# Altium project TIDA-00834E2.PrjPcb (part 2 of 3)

## Sheet TIDA-00834E2_Pg6_VOLTAGE2.SchDoc: VOLTAGE3, VOLTAGE4 AND ZCD
size 431 x 279 mm; Date: Not shown in title block; ApprovedBy: Not shown in title block; CheckedBy: Not shown in title block; Author: Not shown in title block; CompanyName: Not shown in title block; DrawnBy: Sreenivasa; Engineer: Not shown in title block; Organization: Not shown in title block; Address1: Not shown in title block; Address2: Not shown in title block; Address3: Not shown in title block; Address4: Not shown in title block; DocumentNumber: 1; Revision: Use project parameter SCH_Rev; SheetNumber: 6; SheetTotal: 10; PageSetup: Record=PageOptions¦CenterHorizontal=True¦CenterVertical=True¦PrintScale=1.00¦XCorrection=1.00¦YCorrection=1.00¦PrintKind=0¦BorderSize=5000000¦LeftOffset=0¦BottomOffset=0¦Orientation=2¦PaperLength=1000¦PaperWidth=1000¦Scale=100¦PaperSource=15¦PrintQuality=600¦MediaType=1¦DitherType=10¦PaperKind=Letter¦PrintScaleMode=1
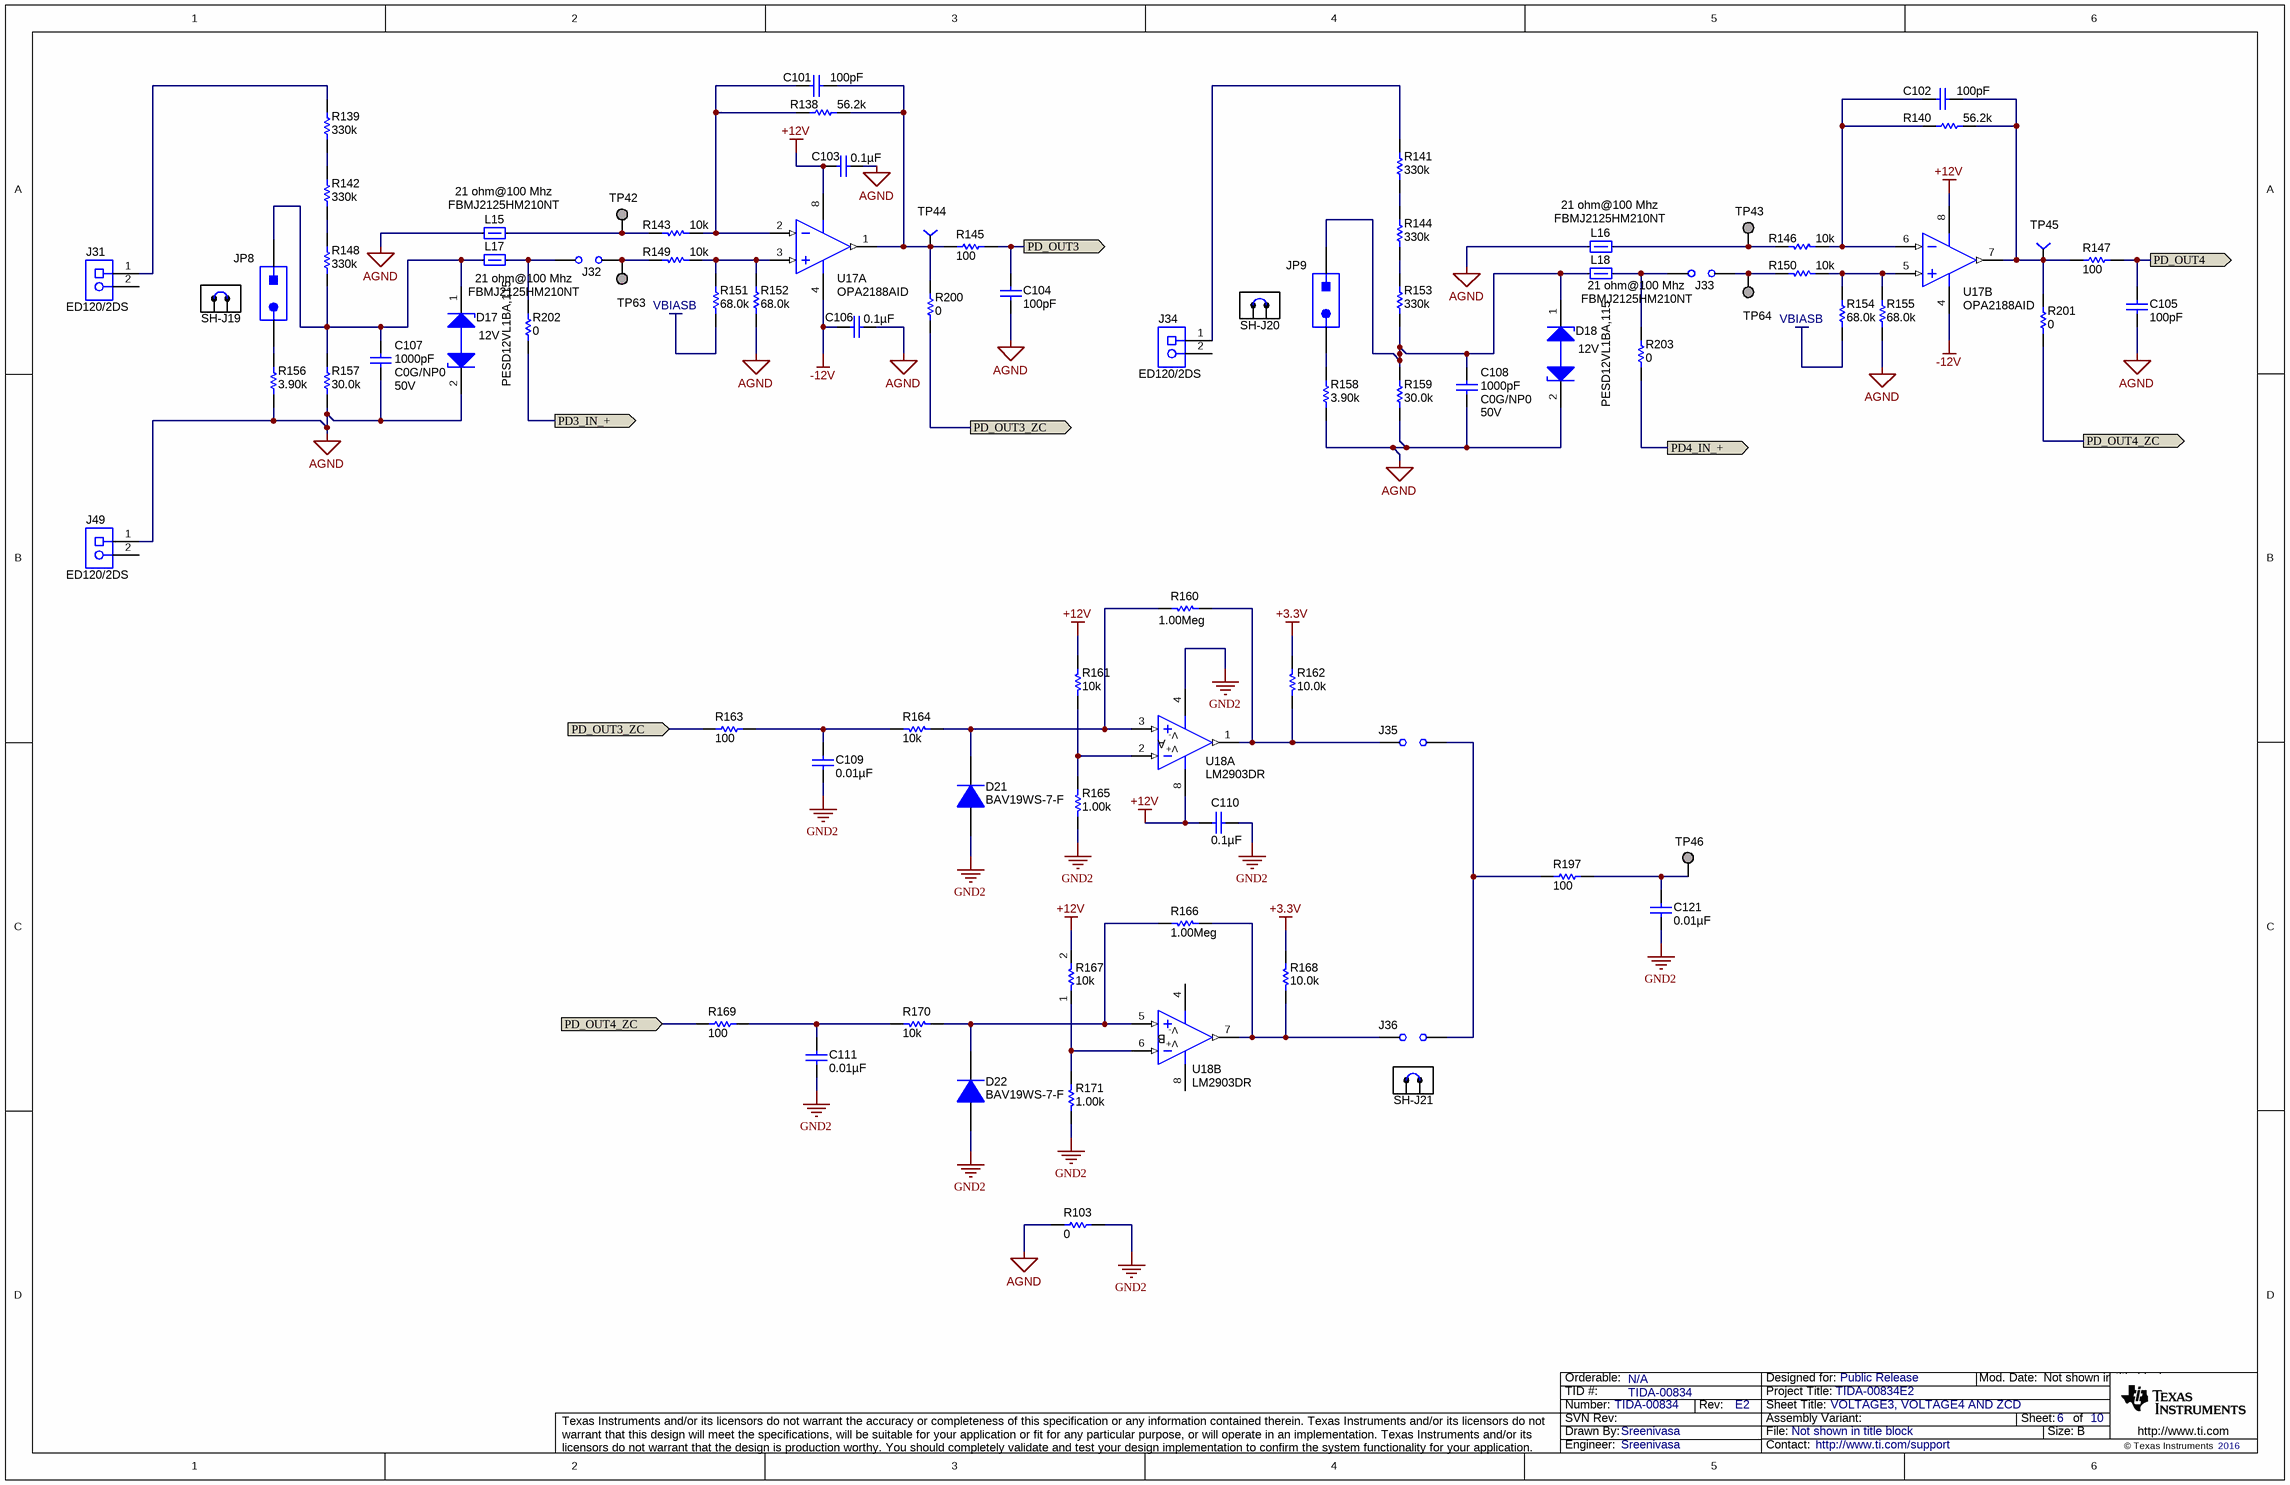
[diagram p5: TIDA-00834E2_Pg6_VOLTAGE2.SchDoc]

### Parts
C101  ValueDisplayed: 100pF  [0603]  (hidden comment: 06033C101KAT2A)
C102  ValueDisplayed: 100pF  [0603]  (hidden comment: 06033C101KAT2A)
C103  ValueDisplayed: 0.1µF  [0603]  (hidden comment: 06033C104JAT2A)
C104  ValueDisplayed: 100pF  [0603]  (hidden comment: 06033C101KAT2A)
C105  ValueDisplayed: 100pF  [0603]  (hidden comment: 06033C101KAT2A)
C106  ValueDisplayed: 0.1µF  [0603]  (hidden comment: 06033C104JAT2A)
C107  ValueDisplayed: 1000pF  Value2: 50V  TempCo: C0G/NP0  [0603]  (hidden comment: C1608C0G1H102J080AA)
C108  ValueDisplayed: 1000pF  Value2: 50V  TempCo: C0G/NP0  [0603]  (hidden comment: C1608C0G1H102J080AA)
C109  ValueDisplayed: 0.01µF  [0603]  (hidden comment: C1608C0G1E103J080AA)
C110  ValueDisplayed: 0.1µF  [0603]  (hidden comment: 06033C104JAT2A)
C111  ValueDisplayed: 0.01µF  [0603]  (hidden comment: C1608C0G1E103J080AA)
C121  ValueDisplayed: 0.01µF  [0603]  (hidden comment: C1608C0G1E103J080AA)
D17  value 12V  [SOD-323]  (hidden comment: PESD12VL1BA,115)
D18  value 12V  [SOD-323]  (hidden comment: PESD12VL1BA,115)
D21  BAV19WS-7-F  [SOD-323]
D22  BAV19WS-7-F  [SOD-323]
J31  ED120/2DS  [CONN_ED120-2DS]
J32  JUMPER_2X100MIL  [HDR100_1X2]  (value not drawn)
J33  JUMPER_2X100MIL  [HDR100_1X2]  (value not drawn)
J34  ED120/2DS  [CONN_ED120-2DS]
J35  JUMPER_2X100MIL  [HDR100_1X2]  (value not drawn)
J36  JUMPER_2X100MIL  [HDR100_1X2]  (value not drawn)
J49  ED120/2DS  [CONN_ED120-2DS]
JP8  5-146280-2  [TSW-102-07-G-S]  (value not drawn)
JP9  5-146280-2  [TSW-102-07-G-S]  (value not drawn)
L15  value 21 ohm@100 Mhz  [0805_HV]  (hidden comment: FBMJ2125HM210NT)
L16  value 21 ohm@100 Mhz  [0805_HV]  (hidden comment: FBMJ2125HM210NT)
L17  value 21 ohm@100 Mhz  [0805_HV]  (hidden comment: FBMJ2125HM210NT)
L18  value 21 ohm@100 Mhz  [0805_HV]  (hidden comment: FBMJ2125HM210NT)
R103  value 0  [0805_HV]  (hidden comment: CRCW08050000Z0EA)
R138  ValueDisplayed: 56.2k  [0603]  (hidden comment: CRCW060356K2FKEA)
R139  ValueDisplayed: 330k  [1206]  (hidden comment: RC1206FR-07330KL)
R140  ValueDisplayed: 56.2k  [0603]  (hidden comment: CRCW060356K2FKEA)
R141  ValueDisplayed: 330k  [1206]  (hidden comment: RC1206FR-07330KL)
R142  ValueDisplayed: 330k  [1206]  (hidden comment: RC1206FR-07330KL)
R143  value 10k  [0603]  (hidden comment: CRCW060310K0FKEA)
R144  ValueDisplayed: 330k  [1206]  (hidden comment: RC1206FR-07330KL)
R145  value 100  [0603]  (hidden comment: CRCW0603100RFKEA)
R146  value 10k  [0603]  (hidden comment: CRCW060310K0FKEA)
R147  value 100  [0603]  (hidden comment: CRCW0603100RFKEA)
R148  ValueDisplayed: 330k  [1206]  (hidden comment: RC1206FR-07330KL)
R149  value 10k  [0603]  (hidden comment: CRCW060310K0FKEA)
R150  value 10k  [0603]  (hidden comment: CRCW060310K0FKEA)
R151  ValueDisplayed: 68.0k  [0603]  (hidden comment: RC0603FR-0768KL)
R152  ValueDisplayed: 68.0k  [0603]  (hidden comment: RC0603FR-0768KL)
R153  ValueDisplayed: 330k  [1206]  (hidden comment: RC1206FR-07330KL)
R154  ValueDisplayed: 68.0k  [0603]  (hidden comment: RC0603FR-0768KL)
R155  ValueDisplayed: 68.0k  [0603]  (hidden comment: RC0603FR-0768KL)
R156  ValueDisplayed: 3.90k  [0603]  (hidden comment: CRCW06033K90FKEA)
R157  ValueDisplayed: 30.0k  [0603]  (hidden comment: RC0603FR-0730KL)
R158  ValueDisplayed: 3.90k  [0603]  (hidden comment: CRCW06033K90FKEA)
R159  ValueDisplayed: 30.0k  [0603]  (hidden comment: RC0603FR-0730KL)
R160  value 1.00Meg  [0603]  (hidden comment: CRCW06031M00FKEA)
R161  value 10k  [0603]  (hidden comment: CRCW060310K0FKEA)
R162  value 10.0k  [0603]  (hidden comment: CRCW060310K0FKEA)
R163  value 100  [0603]  (hidden comment: CRCW0603100RFKEA)
R164  value 10k  [0603]  (hidden comment: CRCW060310K0FKEA)
R165  value 1.00k  [1206]  (hidden comment: CRCW12061K00FKEA)
R166  value 1.00Meg  [0603]  (hidden comment: CRCW06031M00FKEA)
R167  value 10k  [0603]  (hidden comment: CRCW060310K0FKEA)
R168  value 10.0k  [0603]  (hidden comment: CRCW060310K0FKEA)
R169  value 100  [0603]  (hidden comment: CRCW0603100RFKEA)
R170  value 10k  [0603]  (hidden comment: CRCW060310K0FKEA)
R171  value 1.00k  [1206]  (hidden comment: CRCW12061K00FKEA)
R197  value 100  [0603]  (hidden comment: CRCW0603100RFKEA)
R200  ValueDisplayed: 0  [0603]  (hidden comment: RC0603JR-070RL)
R201  ValueDisplayed: 0  [0603]  (hidden comment: RC0603JR-070RL)
R202  ValueDisplayed: 0  [0603]  (hidden comment: RC0603JR-070RL)
R203  ValueDisplayed: 0  [0603]  (hidden comment: RC0603JR-070RL)
SH-J19  881545-2  [TE_881545-2]  (value not drawn)  (mechanical)
SH-J20  881545-2  [TE_881545-2]  (value not drawn)  (mechanical)
SH-J21  881545-2  [TE_881545-2]  (value not drawn)  (mechanical)
TP42  Suggest using a net name here  [Keystone1573-2]  (value not drawn)
TP43  Suggest using a net name here  [Keystone1573-2]  (value not drawn)
TP44  TP-040_RND  [TP_H045P075]  (value not drawn)
TP45  TP-040_RND  [TP_H045P075]  (value not drawn)
TP46  Suggest using a net name here  [Keystone1573-2]  (value not drawn)
TP63  Suggest using a net name here  [Keystone1573-2]  (value not drawn)
TP64  Suggest using a net name here  [Keystone1573-2]  (value not drawn)
U17  OPA2188AID  [D0008A_N]  (parts A,B of 2)
U18  LM2903DR  [D0008A_N]  (parts A,B of 2)

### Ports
PD3_IN_+ (out), PD4_IN_+ (out), PD_OUT3 (out), PD_OUT3_ZC (in), PD_OUT3_ZC (out), PD_OUT4 (out), PD_OUT4_ZC (in), PD_OUT4_ZC (out)

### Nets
+3.3V: R162.2 R168.2
+12V: C103.2 C110.2 R161.2 R167.2 U17.8(V+) U18.8(V+)
-12V: C106.2 U17.4(V-)
AGND: C103.1 C104.2 C105.2 C106.1 C107.1 C108.1 D17.2(K) D18.2(K) J49.1 L15.1 L16.1 R103.1 R152.1 R155.1 R156.1 R157.1 R158.1 R159.1
GND2: C109.1 C110.1 C111.1 C121.1 D21.2(A) D22.2(A) R103.2 R165.1 R171.1 U18.4(V-)
VBIASB: R151.1 R154.1
PD3_IN_+: R202.1 ; port PD3_IN_+
PD4_IN_+: R203.1 ; port PD4_IN_+
PD_OUT3: C104.1 R145.2 ; port PD_OUT3
PD_OUT3_ZC: R163.1 R200.1 ; port PD_OUT3_ZC
PD_OUT4: C105.1 R147.2 ; port PD_OUT4
PD_OUT4_ZC: R169.1 R201.1 ; port PD_OUT4_ZC
NetC101_1: C101.1 R138.2 R143.1 U17.2(IN_A-)
NetC101_2: C101.2 R138.1 R145.1 R200.2 TP44.1 U17.1(OUT_A)
NetC102_1: C102.1 R140.2 R146.1 U17.6(IN_B-)
NetC102_2: C102.2 R140.1 R147.1 R201.2 TP45.1 U17.7(OUT_B)
NetC107_2: C107.2 D17.1(K) JP8.1 L17.1 R148.1 R157.2
NetC108_2: C108.2 D18.1(K) JP9.1 L18.1 R153.1 R159.2
NetC109_2: C109.2 R163.2 R164.1
NetC111_2: C111.2 R169.2 R170.1
NetC121_2: C121.2 R197.2 TP46.1
NetD21_1: D21.1(K) R160.2 R164.2 U18.3(IN+)
NetD22_1: D22.1(K) R166.2 R170.2 U18.5(IN+)
NetJ31_1: J31.1 R139.2
NetJ32_1: J32.1 R149.2 TP63.1
NetJ32_2: J32.2 L17.2 R202.2
NetJ33_1: J33.1 R150.2 TP64.1
NetJ33_2: J33.2 L18.2 R203.2
NetJ34_1: J34.1 R141.2
NetJ35_1: J35.1 R160.1 R162.1 U18.1(OUT)
NetJ35_2: J35.2 J36.2 R197.1
NetJ36_1: J36.1 R166.1 R168.1 U18.7(OUT)
NetJP8_2: JP8.2 R156.2
NetJP9_2: JP9.2 R158.2
NetL15_2: L15.2 R143.2 TP42.1
NetL16_2: L16.2 R146.2 TP43.1
NetR139_1: R139.1 R142.2
NetR141_1: R141.1 R144.2
NetR142_1: R142.1 R148.2
NetR144_1: R144.1 R153.2
NetR149_1: R149.1 R151.2 R152.2 U17.3(IN_A+)
NetR150_1: R150.1 R154.2 R155.2 U17.5(IN_B+)
NetR161_1: R161.1 R165.2 U18.2(IN-)
NetR167_1: R167.1 R171.2 U18.6(IN-)

Not connected (* = marked no-connect by the designer): J31 2; J34 2; J49 2

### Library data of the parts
C101 C102 C104 C105 = 06033C101KAT2A: CAP, CERM, 100pF, 25V, +/-10%, X7R, 0603; Manufacturer: AVX; Polarized: N; CompType: Capacitor; U/M: EA; Cap_F: 0.0000000001; Tolerance_%: 10; Value1: Unknown; VDC_V: 25; TaMin_C: -55; TaMax_C: 125
C103 C106 C110 = 06033C104JAT2A: CAP, CERM, 0.1uF, 25V, +/-5%, X7R, 0603; Manufacturer: AVX; Polarized: N; CompType: Capacitor; U/M: EA; Cap_F: 0.0000001; Tolerance_%: 5; ESR_Ohm: 0.05; Value1: 0.05 ohm; VDC_V: 25; TaMin_C: -55; TaMax_C: 125
C107 C108 = C1608C0G1H102J: CAP, CERM, 1000pF, 50V, +/-5%, C0G/NP0, 0603; Manufacturer: TDK; Polarized: N; CompType: Capacitor; U/M: EA; Cap_F: 0.000000001; Tolerance_%: 5; ESR_Ohm: 0.0563; Value1: 0.0563 ohm; VDC_V: 50; TaMin_C: -55; TaMax_C: 125
C109 C111 C121 = C1608C0G1E103J: CAP, CERM, 0.01uF, 25V, +/-5%, C0G/NP0, 0603; Manufacturer: TDK; Polarized: N; CompType: Capacitor; U/M: EA; Cap_F: 0.00000001; Tolerance_%: 5; Value1: Unknown; VDC_V: 25; TaMin_C: -55; TaMax_C: 125
D17 D18 = PESD3V3L1BA: TVS DIODE 12VWM 37VC SOD323; Manufacturer: NXP Semiconductor; SymbolCreator: x0199378
D21 D22 = BAV19WS-7-F: Diode, Switching, 100 V, 0.2 A, SOD-323; Manufacturer: Diodes Inc.; U/M: EA; Vf_V: 1.25; Value: 100V; Value1: 0.2A; Value2: 1.25V; Io_A: 0.2; Vr_V: 100; TJmax_C: 150; SizeAreaWB_mm2: 8.695; SizeArea_mm2: 3.645; SizeX_mm: 2.7; SizeY_mm: 1.35; SizeZ_mm: 1; AEC Category: Q101
J31 J34 J49 = ED120/2DS: TERMINAL BLOCK 5.08MM VERT 2POS, TH; Manufacturer: On-Shore Technology; SymbolCreator: a0412235; U/M: EA
J32 J33 J35 J36 = JUMPER_2X100MIL: Header, Male 2-pin, 100mil spacing,; Manufacturer: Sullins; PartNumber: PEC02SAAN; area: 20000; Value: PEC02SAAN
JP8 JP9 = TSW-102-07-G-S: Header, 100mil, 2x1, Gold, TH; Manufacturer: TE Connectivity; SymbolCreator: a0412235; U/M: EA
L15-L18 = FBMJ2125HM210NT: Ferrite Bead, 21 ohm @ 100 MHz, 6 A, 0805; Manufacturer: Taiyo Yuden; Imax_A: 6; DCR_ohm: 0.004; Value1: 0.004 ohm; Value2: 6A; ZTyp@100MHz_Ohm: 21
R103 = CRCW0805330KJNEA: RES, 0 ohm, 5%, 0.125W, 0805; Manufacturer: Vishay-Dale; CompType: Resistor; Tolerance_%: 5; Power_W: 0.125; VDC_V: 150; TempCo: 200 ppm/C; EIA_Code: E24; U/M: EA
R138 R140 = CRCW060356K2FKEA: RES, 56.2 k, 1%, 0.1 W, 0603; Manufacturer: Vishay-Dale; CompType: Resistor; Value: 56.2k; Res_ohm: 56200; Value_Code: 56k2; Tolerance_%: 1; Power_W: 0.1; Value2: 0.1W; VDC_V: 75; TempCo: 100 ppm/C; SizeArea_mm2: 1.28; SizeX_mm: 1.6; SizeY_mm: 0.8; EIA_Code: E96; U/M: EA; AEC Category: Q200
R139 R141 R142 R144 R148 R153 = RC1206FR-07330KL: RES, 330 k, 1%, 0.25 W, 1206; Manufacturer: Yageo America; CompType: Resistor; Value: 330k; Res_ohm: 330000; Tolerance_%: 1; Power_W: 0.25; Value2: 0.25W; VDC_V: 200; TempCo: 100 ppm/C; U/M: EA
R143 R146 R149 R150 R161 R164 R167 R170 = RNCF0603TKY10K0: RES, 10.0k ohm, 1%, 0.1W, 0603; Manufacturer: Stackpole Electronics Inc; CompType: Resistor; Res_ohm: 10000; Value_Code: 10k0; Tolerance_%: 0.01; Value1: 0.01%; Power_W: 0.063; Value2: 0.063W; VDC_V: 50; TempCo: 5 ppm/C; U/M: EA
R145 R147 R163 R169 R197 = CRCW0603100RFKEA: RES, 100 ohm, 1%, 0.1W, 0603; Manufacturer: Vishay-Dale; CompType: Resistor; Value_Code: 100R; Tolerance_%: 1; Power_W: 0.1; VDC_V: 75; TempCo: 100 ppm/C; EIA_Code: E96; U/M: EA
R151 R152 R154 R155 = RC0603FR-0768KL: RES, 68.0 k, 1%, 0.1 W, 0603; Manufacturer: Yageo America; CompType: Resistor; Value: 68.0k; Res_ohm: 68000; Value_Code: 68k0; Tolerance_%: 1; Power_W: 0.1; Value2: 0.1W; VDC_V: 150; TempCo: 200 ppm/C; SizeArea_mm2: 1.28; SizeX_mm: 1.6; SizeY_mm: 0.8; U/M: EA; AEC Category: Q200
R156 R158 = CRCW06033K90FKEA: RES, 3.90 k, 1%, 0.1 W, 0603; Manufacturer: Vishay-Dale; CompType: Resistor; Value: 3.90k; Res_ohm: 3900; Value_Code: 3k90; Tolerance_%: 1; Power_W: 0.1; Value2: 0.1W; TempCo: 100 ppm/C; SizeArea_mm2: 1.28; SizeX_mm: 1.6; SizeY_mm: 0.8; U/M: EA; AEC Category: Q200
R157 R159 = RC0603FR-0730KL: RES, 30.0 k, 1%, 0.1 W, 0603; Manufacturer: Yageo America; CompType: Resistor; Value: 30.0k; Res_ohm: 30000; Value_Code: 30k0; Tolerance_%: 1; Power_W: 0.1; Value2: 0.1W; VDC_V: 150; TempCo: 200 ppm/C; SizeArea_mm2: 1.28; SizeX_mm: 1.6; SizeY_mm: 0.8; U/M: EA; AEC Category: Q200
R160 R166 = CRCW06031M00FKEA: RES, 1.00Meg ohm, 1%, 0.1W, 0603; Manufacturer: Vishay-Dale; CompType: Resistor; Res_ohm: 1000000; Value_Code: 1M00; Tolerance_%: 1; Power_W: 0.1; VDC_V: 75; TempCo: 100 ppm/C; EIA_Code: E96; U/M: EA
R162 R168 = CRCW060310K0FKEA: RES, 10.0k ohm, 1%, 0.1W, 0603; Manufacturer: Vishay-Dale; CompType: Resistor; Res_ohm: 10000; Value_Code: 10k0; Tolerance_%: 1; Power_W: 0.1; VDC_V: 75; TempCo: 100 ppm/C; EIA_Code: E96; U/M: EA
R165 R171 = CRCW12061K00FKEA: RES, 1.00k ohm, 1%, 0.25W, 1206; Manufacturer: Vishay-Dale; CompType: Resistor; Res_ohm: 1000; Value_Code: 1k00; Tolerance_%: 1; Power_W: 0.25; VDC_V: 200; TempCo: 100 ppm/C; EIA_Code: E96; U/M: EA
R200-R203 = RC0603JR-070RL: RES, 0, 5%, 0.1 W, 0603; Manufacturer: Yageo America; CompType: Resistor; Value: 0; Value_Code: 0000; Tolerance_%: 5; Power_W: 0.1; Value2: 0.1W; VDC_V: 50; TempCo: 200 ppm/C; EIA_Code: E24; U/M: EA; AEC Category: Q200
SH-J19-SH-J21 = 881545-2: Shunt, 100mil, Gold plated, Black; Manufacturer: TE Connectivity
TP42 TP43 TP46 TP63 TP64 = 1573-2: Terminal, Turret, TH, Double; Manufacturer: Keystone; CompType: Turret Terminal; U/M: EA
TP44 TP45 = TP-040_RND: Test Point, O.040 Hole; Manufacturer: STD; Value: STD
U17 = OPA2188AID: 0.03 uV/degC, 6 uV Vos, Low Noise, Rail-to-Rail Output, Zero-Drift Operational Amplifier, 4 to 36 V, -40 to 105 degC, 8-pin SOIC (D0008A), Green (RoHS & no Sb/Br); Manufacturer: Texas Instruments; Alternate PartNumber: Equivalent; CMRR(Min)(dB): 120; GBW(Typ)(MHz): 2; IIB(Max)(pA): 850; Iq per channel(Max)(mA): 0.475; Offset Drift(Typ)(uV/C): 0.03; Packing: TUBE; Rating: Catalog; Slew Rate(Typ)(V/us): 0.8; Sub Family: High Supply Voltage Amplifier (>=30V), Low Noise Amp (<=10nV/rtHz), Low Offset Voltage Amplifier (<=500uV), Low Power Amp (<=500uA), Precision Amplifier, Zero Drift Precision Amplifier; Total Supply Voltage(Max)(+5V is 5, +/-5V is 10): 36; Total Supply Voltage(Min)(+5V is 5, +/-5V is 10): 4; Vio (25C)(Max)(mV): 0.025
U18 = LM2903D: Dual Comparator, D0008A; Manufacturer: Texas Instruments; CompType: OpAmp IC

## Sheet TIDA-00834E2_Pg7_Split Rail Converter.SchDoc: SPLIT RAIL CONVERTER
size 431 x 279 mm; Date: Not shown in title block; ApprovedBy: Not shown in title block; CheckedBy: Not shown in title block; Author: Not shown in title block; CompanyName: Not shown in title block; DrawnBy: Sreenivasa; Engineer: Not shown in title block; Organization: Not shown in title block; Address1: Not shown in title block; Address2: Not shown in title block; Address3: Not shown in title block; Address4: Not shown in title block; DocumentNumber: 1; Revision: Use project parameter SCH_Rev; SheetNumber: 7; SheetTotal: 10; PageSetup: Record=PageOptions¦CenterHorizontal=True¦CenterVertical=True¦PrintScale=1.00¦XCorrection=1.00¦YCorrection=1.00¦PrintKind=0¦BorderSize=5000000¦LeftOffset=0¦BottomOffset=0¦Orientation=2¦PaperLength=1000¦PaperWidth=1000¦Scale=100¦PaperSource=15¦PrintQuality=600¦MediaType=1¦DitherType=10¦PaperKind=Letter¦PrintScaleMode=1
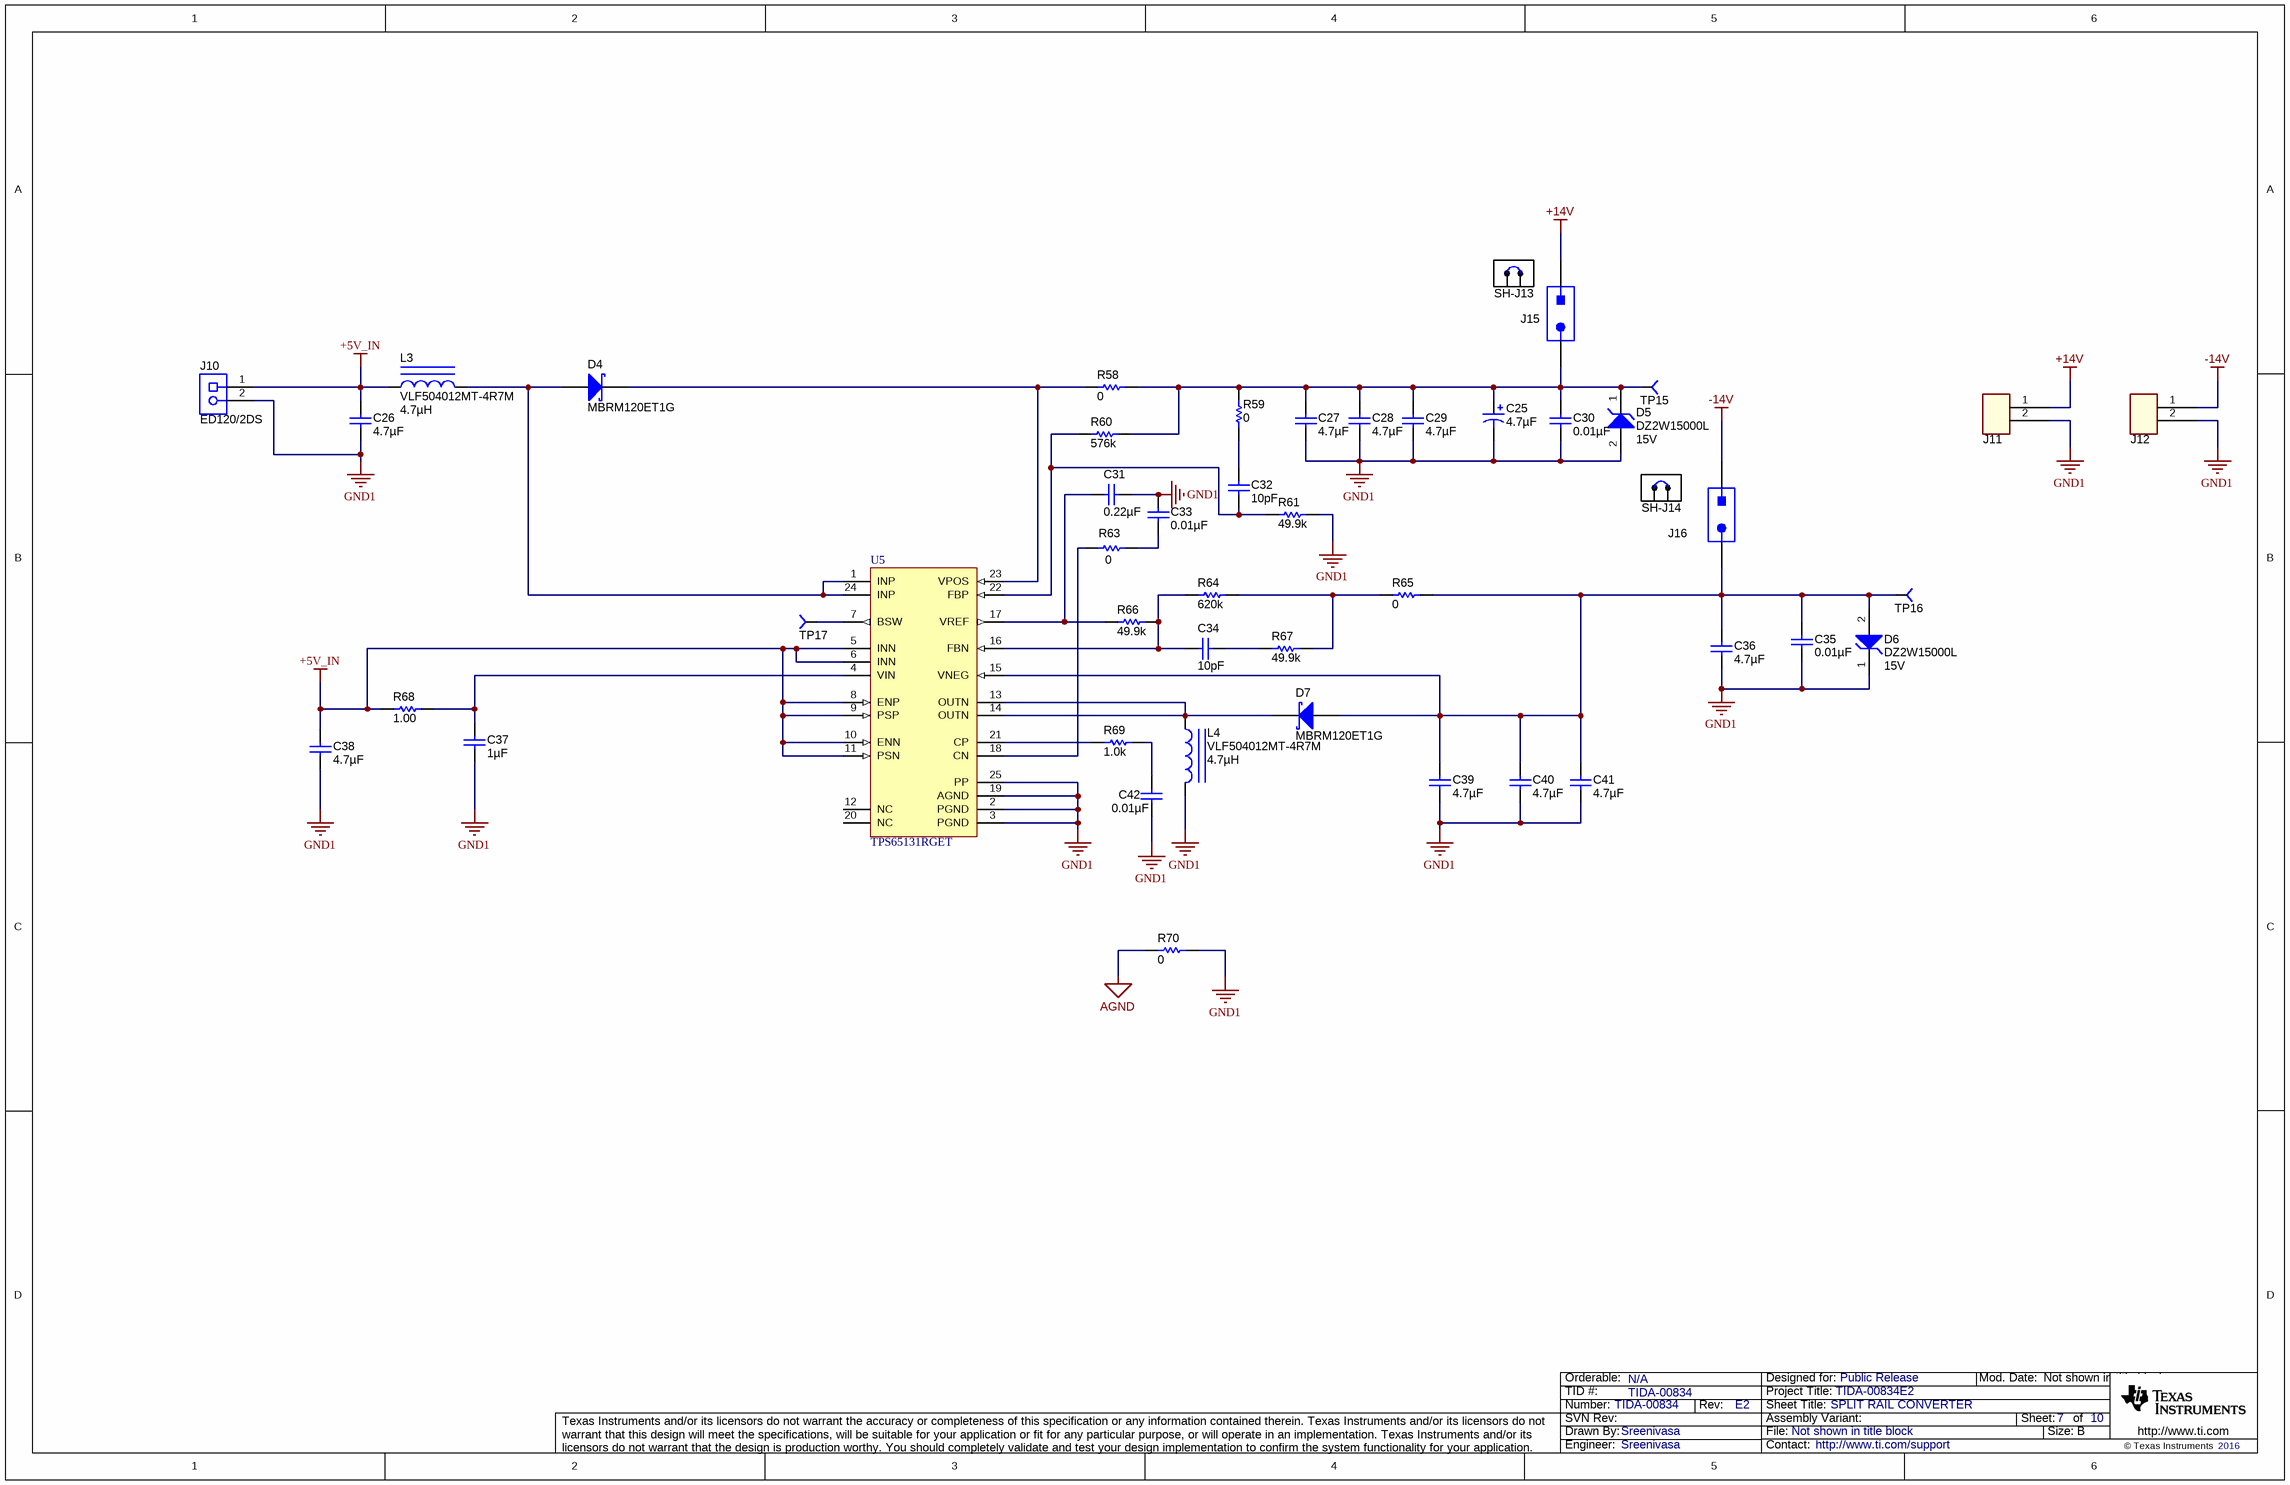
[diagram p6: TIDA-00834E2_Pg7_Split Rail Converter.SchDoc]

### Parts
C25  ValueDisplayed: 4.7µF  [6032-28]  (hidden comment: 293D475X9025C2TE3)
C26  ValueDisplayed: 4.7µF  [1206]  (hidden comment: C3216X7R1E475M160AC)
C27  ValueDisplayed: 4.7µF  [1206]  (hidden comment: C3216X7R1E475M160AC)
C28  ValueDisplayed: 4.7µF  [1206]  (hidden comment: C3216X7R1E475M160AC)
C29  ValueDisplayed: 4.7µF  [1206]  (hidden comment: C3216X7R1E475M160AC)
C30  ValueDisplayed: 0.01µF  [0603]  (hidden comment: GRM188R70J103KA01D)
C31  ValueDisplayed: 0.22µF  [0603]  (hidden comment: C0603C224K9RACTU)
C32  ValueDisplayed: 10pF  [0603]  (hidden comment: C0603C100J5GACTU)
C33  ValueDisplayed: 0.01µF  [0603]  (hidden comment: GRM188R70J103KA01D)
C34  ValueDisplayed: 10pF  [0603]  (hidden comment: C0603C100J5GACTU)
C35  ValueDisplayed: 0.01µF  [0603]  (hidden comment: GRM188R70J103KA01D)
C36  ValueDisplayed: 4.7µF  [1206]  (hidden comment: C3216X7R1E475M160AC)
C37  ValueDisplayed: 1µF  [0603]  (hidden comment: GRM188R61E105KA12D)
C38  ValueDisplayed: 4.7µF  [1206]  (hidden comment: C3216X7R1E475M160AC)
C39  ValueDisplayed: 4.7µF  [1206]  (hidden comment: C3216X7R1E475M160AC)
C40  ValueDisplayed: 4.7µF  [1206]  (hidden comment: C3216X7R1E475M160AC)
C41  ValueDisplayed: 4.7µF  [1206]  (hidden comment: C3216X7R1E475M160AC)
C42  ValueDisplayed: 0.01µF  [0603]  (hidden comment: GRM188R70J103KA01D)
D4  MBRM120ET1G  [POWERMITE]
D5  DZ2W15000L  value 15V  [SOD-123]
D6  DZ2W15000L  value 15V  [SOD-123]
D7  MBRM120ET1G  [POWERMITE]
J10  ED120/2DS  [CONN_ED120-2DS]
J11  CON-OSTVN02A150  [CN2_MTB_P100_PD80_D1.1_S5.54X6.5_STACK]  (value not drawn)
J12  CON-OSTVN02A150  [CN2_MTB_P100_PD80_D1.1_S5.54X6.5_STACK]  (value not drawn)
J15  5-146280-2  [TSW-102-07-G-S]  (value not drawn)
J16  5-146280-2  [TSW-102-07-G-S]  (value not drawn)
L3  VLF504012MT-4R7M  ValueDisplayed: 4.7µH  [IND_VLF504012]
L4  VLF504012MT-4R7M  ValueDisplayed: 4.7µH  [IND_VLF504012]
R58  value 0  [1206]  (hidden comment: CRCW12060000Z0EA)
R59  ValueDisplayed: 0  [0603]  (hidden comment: CRCW06030000Z0EA)
R60  ValueDisplayed: 576k  [0603]  (hidden comment: CRCW0603576KFKEA)
R61  ValueDisplayed: 49.9k  [0603]  (hidden comment: RG1608P-4992-B-T5)
R63  ValueDisplayed: 0  [0603]  (hidden comment: CRCW06030000Z0EA)
R64  ValueDisplayed: 620k  [0603]  (hidden comment: CRCW0603620KFKEA)
R65  ValueDisplayed: 0  [0603]  (hidden comment: CRCW06030000Z0EA)
R66  ValueDisplayed: 49.9k  [0603]  (hidden comment: RG1608P-4992-B-T5)
R67  ValueDisplayed: 49.9k  [0603]  (hidden comment: RG1608P-4992-B-T5)
R68  ValueDisplayed: 1.00  [0603]  (hidden comment: CR0603-J/-1R0ELF)
R69  ValueDisplayed: 1.0k  [0603]  (hidden comment: CRCW06031K00JNEA)
R70  value 0  [0805_HV]  (hidden comment: CRCW08050000Z0EA)
SH-J13  881545-2  [TE_881545-2]  (value not drawn)  (mechanical)
SH-J14  881545-2  [TE_881545-2]  (value not drawn)  (mechanical)
TP15  TP-5001-BLACK  [TH-40]  (value not drawn)
TP16  TP-5001-BLACK  [TH-40]  (value not drawn)
TP17  TP-040_RND  [TP-040_RND]  (value not drawn)
U5  TPS65131RGET  [RGE0024B]

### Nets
+5V_IN: C26.1 C38.1 J10.1 L3.1 R68.1 U5.5(INN) U5.6(INN) U5.8(ENP) U5.9(PSP) U5.10(ENN) U5.11(PSN)
+14V: J11.1 J15.1
-14V: J12.1 J16.1
AGND: R70.1
GND1: C25.2(-) C26.2 C27.2 C28.2 C29.2 C30.2 C31.1 C33.1 C35.2 C36.2 C37.2 C38.2 C39.2 C40.2 C41.2 C42.2 D5.2(A) D6.1(K) J10.2 J11.2 J12.2 L4.2 R61.2 R70.2 U5.2(PGND) U5.3(PGND) U5.19(AGND) U5.25(PP)
NetC25_1: C25.1(+) C27.1 C28.1 C29.1 C30.1 D5.1(K) J15.2 R58.2 R59.2 R60.2 TP15.1
NetC31_2: C31.2 R66.1 U5.17(VREF)
NetC32_1: C32.1 R59.1
NetC32_2: C32.2 R60.1 R61.1 U5.22(FBP)
NetC33_2: C33.2 R63.2
NetC34_1: C34.1 R67.1
NetC34_2: C34.2 R64.1 R66.2 U5.16(FBN)
NetC35_1: C35.1 C36.1 C39.1 C40.1 C41.1 D6.2(A) D7.2(A) J16.2 R65.2 TP16.1 U5.15(VNEG)
NetC37_1: C37.1 R68.2 U5.4(VIN)
NetC42_1: C42.1 R69.2
NetD4_1: D4.1(K) R58.1 U5.23(VPOS)
NetD4_2: D4.2(A) L3.2 U5.1(INP) U5.24(INP)
NetD7_1: D7.1(K) L4.1 U5.13(OUTN) U5.14(OUTN)
NetR63_1: R63.1 U5.18(CN)
NetR64_2: R64.2 R65.1 R67.2
NetR69_1: R69.1 U5.21(CP)
NetTP17_1: TP17.1 U5.7(BSW)

Not connected (* = marked no-connect by the designer): U5 12(NC) 20(NC)

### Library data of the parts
C25 = 293D475X9025C2TE3: CAP, TA, 4.7 µF, 25 V, +/- 10%, 2 ohm, SMD; Manufacturer: Vishay-Sprague; Polarized: Y; CompType: Capacitor; Value: 4.7uF; U/M: EA; Cap_F: 0.0000047; Tolerance_%: 10; Value1: 2 ohm; VDC_V: 25; Value2: 25V; ESR_ohm: 2; IRMS_A: 0.24; TaMin_C: -55; TaMax_C: 125; Cap_Case: C
C26-C29 C36 C38-C41 = C3216X7R1E475M: CAP, CERM, 4.7 µF, 25 V, +/- 20%, X7R, 1206; Manufacturer: TDK; Polarized: N; CompType: Capacitor; Value: 4.7uF; U/M: EA; Cap_F: 0.0000047; Tolerance_%: 20; ESR_ohm: 0.0063; Value1: 0.0063 ohm; VDC_V: 25; Value2: 25V; TaMin_C: -55; TaMax_C: 125
C30 C33 C35 C42 = GRM188R70J103KA01D: CAP, CERM, 0.01 µF, 6.3 V, +/- 10%, X7R, 0603; Manufacturer: MuRata; Polarized: N; CompType: Capacitor; Value: 0.01uF; U/M: EA; Cap_F: 0.00000001; Tolerance_%: 10; Value1: Unknown; VDC_V: 6.3; Value2: 6.3V; TaMin_C: -55; TaMax_C: 125
C31 = C0603C224K4RACTU: CAP, CERM, 0.22 µF, 6.3 V, +/- 10%, X7R, 0603; Manufacturer: Kemet; Polarized: N; CompType: Capacitor; Value: 0.22uF; U/M: EA; Cap_F: 0.00000022; Tolerance_%: 10; Value1: Unknown; VDC_V: 16; Value2: 16V; TaMin_C: -55; TaMax_C: 125
C32 C34 = C0603C100J5GACTU: CAP, CERM, 10 pF, 50 V, +/- 5%, C0G/NP0, 0603; Manufacturer: Kemet; Polarized: N; CompType: Capacitor; Value: 10pF; U/M: EA; Cap_F: 0.00000000001; Tolerance_%: 5; Value1: Unknown; VDC_V: 50; Value2: 50V; TaMin_C: -55; TaMax_C: 125
C37 = GRM188R61E105KA12D: CAP, CERM, 1 µF, 25 V, +/- 10%, X5R, 0603; Manufacturer: MuRata; Polarized: N; CompType: Capacitor; Value: 1uF; U/M: EA; Cap_F: 0.000001; Tolerance_%: 10; Value1: Unknown; VDC_V: 25; Value2: 25V; TaMin_C: -55; TaMax_C: 85
D4 D7 = MBRM120ET1G: Diode, Schottky, 20 V, 1 A, POWERMITE; Manufacturer: ON Semiconductor; U/M: EA; Vf_V: 0.53; Value: 20V; Value1: 1A; Value2: 0.53V; Io_A: 1; Vr_V: 20
D5 D6 = DZ2W15000L: Diode, Zener, 15V, 1W, SOD-123; Manufacturer: Panasonic
J10 = ED120/2DS: as J31 on sheet TIDA-00834E2_Pg6_VOLTAGE2
J11 J12 = CON-OSTVN02A150: Terminal Block, 4x1, 2.54mm, TH; Manufacturer: On Shore Technology Inc; SymbolCreator: x0120606
J15 J16 = TSW-102-07-G-S: as JP8 on sheet TIDA-00834E2_Pg6_VOLTAGE2
L3 L4 = VLF504012MT-4R7M: Inductor, Shielded, Ferrite, 4.7uH, 1.83A, 0.1 ohm, SMD; Manufacturer: TDK; Ind_H: 4.7E-6; Imax_A: 1.83; Irms: 1.83A @ 40C rise; Isat: 1.94A @ 30% inductance drop; DCR_ohm: 0.1; Value1: 0.1 ohm; U/M: EA
R58 = CRCW12060000Z0EA: RES, 0 ohm, 5%, 0.25W, 1206; Manufacturer: Vishay-Dale; CompType: Resistor; Value_Code: 0000; Tolerance_%: 5; Power_W: 0.25; VDC_V: 200; TempCo: 200 ppm/C; EIA_Code: E24; U/M: EA
R59 R63 R65 = CRCW06030000Z0EA: RES, 0, 5%, 0.1 W, 0603; Manufacturer: Vishay-Dale; CompType: Resistor; Value: 0; Value_Code: 0000; Tolerance_%: 5; Power_W: 0.1; Value2: 0.1W; VDC_V: 75; TempCo: 200 ppm/C; EIA_Code: E24; U/M: EA
R60 = CRCW0603576KFKEA: RES, 576 k, 1%, 0.1 W, 0603; Manufacturer: Vishay-Dale; CompType: Resistor; Value: 576k; Res_ohm: 576000; Tolerance_%: 1; Power_W: 0.1; Value2: 0.1W; VDC_V: 75; TempCo: 100 ppm/C; EIA_Code: E96; U/M: EA
R61 R66 R67 = RG1608P-4992-B-T5: RES, 49.9 k, 0.1%, 0.1 W, 0603; Manufacturer: Susumu Co Ltd; CompType: Resistor; Value: 49.9k; Res_ohm: 49900; Value_Code: 49k9; Tolerance_%: 0.1; Value2: 0.1W; VDC_V: 75; TempCo: 25 ppm/C; EIA_Code: E192; U/M: EA
R64 = RC0603FR-07620KL: RES SMD 620K OHM 1% 1/10W 0603; Manufacturer: Vishay-Dale; CompType: Resistor; Res_ohm: 620000; Tolerance_%: 1; Power_W: 0.1; Value2: 0.1W; VDC_V: 150; TempCo: 200 ppm/C; U/M: EA
R68 = RT0603DRE071RL: RES SMD 1 OHM 5% 1/10W 0603; Manufacturer: Bourns inc; CompType: Resistor; Value: 1.00; Res_ohm: 1; Value_Code: 1R00; Tolerance_%: 0.5; Value1: 0.5%; Power_W: 0.1; Value2: 0.1W; VDC_V: 75; TempCo: 50 ppm/C; EIA_Code: E192; U/M: EA
R69 = CRCW06031K00JNEA: RES, 1.0 k, 5%, 0.1 W, 0603; Manufacturer: Vishay-Dale; CompType: Resistor; Value: 1.0k; Res_ohm: 1000; Value_Code: 1k00; Tolerance_%: 5; Power_W: 0.1; Value2: 0.1W; VDC_V: 75; TempCo: 200 ppm/C; EIA_Code: E24; U/M: EA
R70 = CRCW0805330KJNEA: as R103 on sheet TIDA-00834E2_Pg6_VOLTAGE2
SH-J13 SH-J14 = 881545-2: as SH-J19-SH-J21 on sheet TIDA-00834E2_Pg6_VOLTAGE2
TP15 TP16 = TP-5001-BLACK: Test Point,  Black, Thru Hole Color Keyed; Manufacturer: Keystone; PartNumber: 5001; area: 10.000; Value: 5001
TP17 = TP-040_RND: as TP44 on sheet TIDA-00834E2_Pg6_VOLTAGE2
U5 = TPS65131RGET: Postive and Negative Output DC-DC Converter, 2.7 to 5.5 V, -40 to 85 degC, 24-pin QFN (RGE24), Green (RoHS & no Sb/Br); Manufacturer: Texas Instruments; Alternate Manufacturer: None; Alternate PartNumber: Equivalent; Iq(Typ)(mA): 0.5; Rating: Catalog; SubFamily: LCD/OLED Display Bias Solutions; Switching Frequency(Typ)(kHz): 1400; Synchronous Rectification: TRUE; Topology: Boost, Inverting Buck/Boost; Vin(Max)(V): 5.5; Vin(Min)(V): 2.7

## Sheet TIDA-00834E2_Pg8_LDO.SchDoc: LDO
size 431 x 279 mm; Date: Not shown in title block; ApprovedBy: Not shown in title block; CheckedBy: Not shown in title block; Author: Not shown in title block; CompanyName: Not shown in title block; DrawnBy: Sreenivasa; Engineer: Not shown in title block; Organization: Not shown in title block; Address1: Not shown in title block; Address2: Not shown in title block; Address3: Not shown in title block; Address4: Not shown in title block; DocumentNumber: 1; Revision: Use project parameter SCH_Rev; SheetNumber: 8; SheetTotal: 10; PageSetup: Record=PageOptions¦CenterHorizontal=True¦CenterVertical=True¦PrintScale=1.00¦XCorrection=1.00¦YCorrection=1.00¦PrintKind=0¦BorderSize=5000000¦LeftOffset=0¦BottomOffset=0¦Orientation=2¦PaperLength=1000¦PaperWidth=1000¦Scale=100¦PaperSource=15¦PrintQuality=600¦MediaType=1¦DitherType=10¦PaperKind=Letter¦PrintScaleMode=1
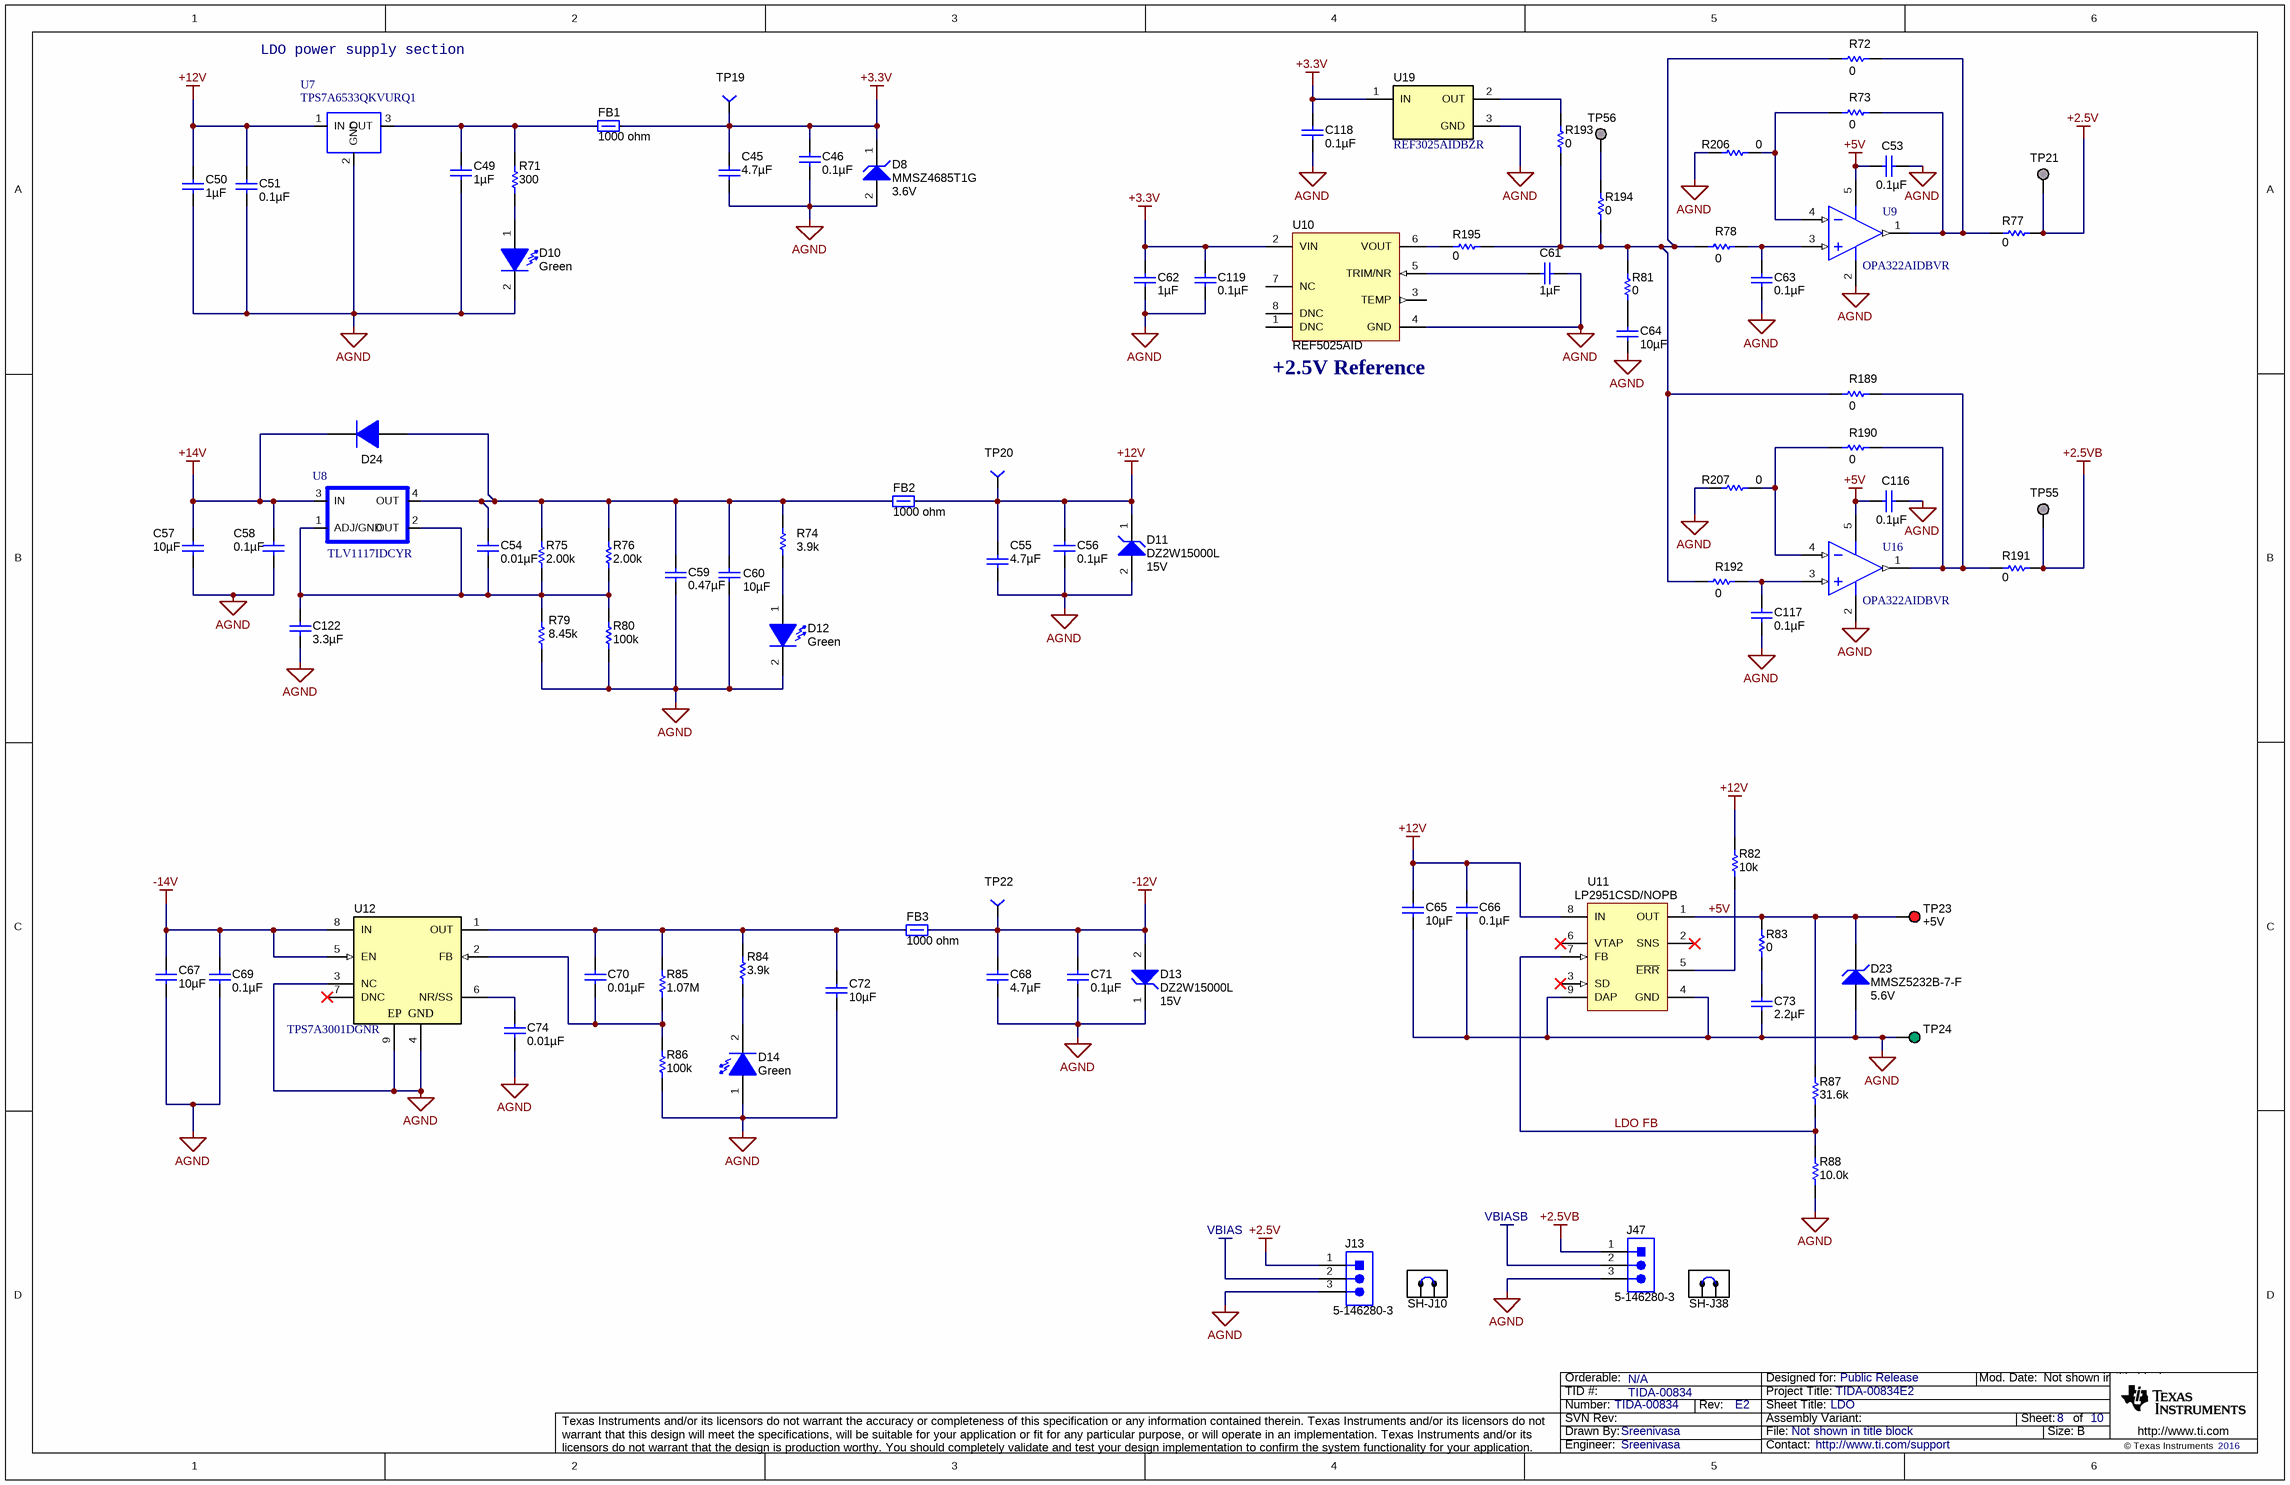
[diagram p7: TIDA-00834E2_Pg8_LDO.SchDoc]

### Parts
C45  ValueDisplayed: 4.7µF  [0805_HV]  (hidden comment: C2012X5R1H475M125AB)
C46  ValueDisplayed: 0.1µF  [0603]  (hidden comment: C0603C104K5RACTU)
C49  ValueDisplayed: 1µF  [0603]  (hidden comment: CGA3E3X5R1H105K080AB)
C50  ValueDisplayed: 1µF  [0603]  (hidden comment: CGA3E3X5R1H105K080AB)
C51  ValueDisplayed: 0.1µF  [0603]  (hidden comment: C0603C104K5RACTU)
C53  ValueDisplayed: 0.1µF  [0603]  (hidden comment: C0603C104J4RACTU)
C54  ValueDisplayed: 0.01µF  [0603]  (hidden comment: 06031C103KAT2A)
C55  ValueDisplayed: 4.7µF  [0805_HV]  (hidden comment: C2012X5R1H475M125AB)
C56  ValueDisplayed: 0.1µF  [0603]  (hidden comment: C0603C104K5RACTU)
C57  ValueDisplayed: 10µF  [1210]  (hidden comment: GMK325AB7106MM-T)
C58  ValueDisplayed: 0.1µF  [0603]  (hidden comment: C0603C104K5RACTU)
C59  ValueDisplayed: 0.47µF  [0603]  (hidden comment: UMK107ABJ474KA-T)
C60  ValueDisplayed: 10µF  [1210]  (hidden comment: GMK325AB7106MM-T)
C61  ValueDisplayed: 1µF  [0805_HV]  (hidden comment: C0805C105K8RACTU)
C62  ValueDisplayed: 1µF  [0805_HV]  (hidden comment: C0805C105K8RACTU)
C63  ValueDisplayed: 0.1µF  [0603]  (hidden comment: C0603C104K8RACTU)
C64  ValueDisplayed: 10µF  [0603]  (hidden comment: EMK107BBJ106MA-T)
C65  ValueDisplayed: 10µF  [1206]  (hidden comment: 885012208069)
C66  ValueDisplayed: 0.1µF  [0603]  (hidden comment: 06033C104JAT2A)
C67  ValueDisplayed: 10µF  [1210]  (hidden comment: GMK325AB7106MM-T)
C68  ValueDisplayed: 4.7µF  [0805_HV]  (hidden comment: C2012X5R1H475M125AB)
C69  ValueDisplayed: 0.1µF  [0603]  (hidden comment: C0603C104K5RACTU)
C70  ValueDisplayed: 0.01µF  [0603]  (hidden comment: 06031C103KAT2A)
C71  ValueDisplayed: 0.1µF  [0603]  (hidden comment: C0603C104K5RACTU)
C72  ValueDisplayed: 10µF  [1210]  (hidden comment: GMK325AB7106MM-T)
C73  ValueDisplayed: 2.2µF  [0805_HV]  (hidden comment: C0805C225K8RACTU)
C74  ValueDisplayed: 0.01µF  [0603]  (hidden comment: 06031C103KAT2A)
C116  ValueDisplayed: 0.1µF  [0603]  (hidden comment: C0603C104J4RACTU)
C117  ValueDisplayed: 0.1µF  [0603]  (hidden comment: C0603C104K8RACTU)
C118  ValueDisplayed: 0.1µF  [0603]  (hidden comment: C0603C104K5RACTU)
C119  ValueDisplayed: 0.1µF  [0603]  (hidden comment: C0603C104K5RACTU)
C122  ValueDisplayed: 3.3µF  [0603]  (hidden comment: C1608X5R1V335K080AC)
D8  MMSZ4685T1G  value 3.6V  [SOD-123]
D10  value Green  [LG L29K_GREEN]  (hidden comment: LG L29K-G2J1-24-Z)
D11  DZ2W15000L  value 15V  [SOD-123]
D12  value Green  [LG L29K_GREEN]  (hidden comment: LG L29K-G2J1-24-Z)
D13  DZ2W15000L  value 15V  [SOD-123]
D14  value Green  [LG L29K_GREEN]  (hidden comment: LG L29K-G2J1-24-Z)
D23  MMSZ5232B-7-F  value 5.6V  [SOD-123]
D24  BAS316,115  [sod-323]  (value not drawn)
FB1  value 1000 ohm  [MMZ1608_095]  (hidden comment: MMZ1608B102CTA00)
FB2  value 1000 ohm  [MMZ1608_095]  (hidden comment: MMZ1608B102CTA00)
FB3  value 1000 ohm  [MMZ1608_095]  (hidden comment: MMZ1608B102CTA00)
J13  5-146280-3  [TE_5-146280-3]
J47  5-146280-3  [TE_5-146280-3]
R71  value 300  [0603]  (hidden comment: CRCW0603300RJNEA)
R72  value 0  [0603]  (hidden comment: CRCW06030000Z0EA)
R73  value 0  [0603]  (hidden comment: CRCW06030000Z0EA)
R74  value 3.9k  [0603]  (hidden comment: CRCW06033K90JNEA)
R75  ValueDisplayed: 2.00k  [1206]  (hidden comment: CRCW12062K00FKEA)
R76  ValueDisplayed: 2.00k  [1206]  (hidden comment: CRCW12062K00FKEA)
R77  value 0  [0603]  (hidden comment: CRCW06030000Z0EA)
R78  value 0  [0603]  (hidden comment: CRCW06030000Z0EA)
R79  ValueDisplayed: 8.45k  [0603]  (hidden comment: CRCW06038K45FKEA)
R80  ValueDisplayed: 100k  [0603]  (hidden comment: CRCW0603100KFKEA)
R81  value 0  [0603]  (hidden comment: CRCW06030000Z0EA)
R82  value 10k  [0603]  (hidden comment: CRCW060310K0FKEA)
R83  value 0  [0603]  (hidden comment: CRCW06030000Z0EA)
R84  value 3.9k  [0603]  (hidden comment: CRCW06033K90JNEA)
R85  ValueDisplayed: 1.07M  [0603]  (hidden comment: CRCW06031M07FKEA)
R86  ValueDisplayed: 100k  [0603]  (hidden comment: RC0603FR-07100KL)
R87  value 31.6k  [0603]  (hidden comment: CRCW060331K6FKEA)
R88  value 10.0k  [0603]  (hidden comment: CRCW060310K0FKEA)
R189  value 0  [0603]  (hidden comment: CRCW06030000Z0EA)
R190  value 0  [0603]  (hidden comment: CRCW06030000Z0EA)
R191  value 0  [0603]  (hidden comment: CRCW06030000Z0EA)
R192  value 0  [0603]  (hidden comment: CRCW06030000Z0EA)
R193  value 0  [0603]  (hidden comment: CRCW06030000Z0EA)
R194  value 0  [0603]  (hidden comment: CRCW06030000Z0EA)
R195  value 0  [0603]  (hidden comment: CRCW06030000Z0EA)
R206  value 0  [0603]  (hidden comment: CRCW06030000Z0EA)
R207  value 0  [0603]  (hidden comment: CRCW06030000Z0EA)
SH-J10  881545-2  [TE_881545-2]  (value not drawn)  (mechanical)
SH-J38  881545-2  [TE_881545-2]  (value not drawn)  (mechanical)
TP19  TP1_PD40_D0.5_S50  [TP1_PD40_D0.5_S50]  (value not drawn)
TP20  TP1_PD40_D0.5_S50  [TP1_PD40_D0.5_S50]  (value not drawn)
TP21  Suggest using a net name here  [Keystone1573-2]  (value not drawn)
TP22  TP1_PD40_D0.5_S50  [TP1_PD40_D0.5_S50]  (value not drawn)
TP23  +5V  [Keystone5010]
TP24  (no value)  [Keystone5126]
TP55  Suggest using a net name here  [Keystone1573-2]  (value not drawn)
TP56  Suggest using a net name here  [Keystone1573-2]  (value not drawn)
U7  TPS7A6533QKVURQ1  [KVU_1]
U8  TLV1117IDCYR  [DCY]
U9  OPA322AIDBVR  [DBV0005A_N]
U10  REF5025AID  [D0008A_N]
U11  LP2951CSD/NOPB  [SDC08A]
U12  TPS7A3001DGNR  [DGN0008D_N]
U16  OPA322AIDBVR  [DBV0005A_N]
U19  REF3025AIDBZR  [DBZ0003A_N]

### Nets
+2.5V: J13.1 R77.1 TP21.1
+2.5VB: J47.1 R191.1 TP55.1
+3.3V: C45.1 C46.1 C62.1 C118.1 C119.1 D8.1(K) FB1.2 TP19.1 U10.2(VIN) U19.1(IN)
+5V: C53.2 C116.2 D23.1(K) R83.2 R87.2 TP23.1 U9.5(V+) U11.1(OUT) U16.5(V+)
+12V: C50.1 C51.1 C55.1 C56.1 C65.1 C66.1 D11.1(K) FB2.2 R82.2 TP20.1 U7.1(IN) U11.8(IN)
+14V: C57.1 C58.1 D24.1(K) U8.3(IN)
-12V: C68.2 C71.1 D13.2(A) FB3.2 TP22.1
-14V: C67.2 C69.1 U12.5(EN) U12.8(IN)
AGND: C45.2 C46.2 C49.2 C50.2 C51.2 C53.1 C55.2 C56.2 C57.2 C58.2 C59.2 C60.2 C61.2 C62.2 C63.1 C64.2 C65.2 C66.2 C67.1 C68.1 C69.2 C71.2 C72.1 C73.2 C74.1 C116.1 C117.1 C118.2 C119.2 C122.2 D8.2(A) D10.2(K) D11.2(A) D12.2(K) D13.1(K) D14.1(A) D23.2(A) J13.3 J47.3 R79.1 R80.1 R86.1 R88.1 R206.2 R207.2 TP24.1 U7.2(GND) U9.2(V-) U10.4(GND) U11.4(GND) U11.9(DAP) U12.3(NC) U12.4(GND) U12.9(EP) U16.2(V-) U19.3(GND)
VBIAS: J13.2
VBIASB: J47.2
LDO FB: R87.1 R88.2 U11.7(FB)
NetC49_1: C49.1 FB1.1 R71.2 U7.3(OUT)
NetC54_1: C54.1 C59.1 C60.1 D24.2(A) FB2.1 R74.2 R75.2 R76.2 U8.4(OUT)
NetC54_2: C54.2 C122.1 R75.1 R76.1 R79.2 R80.2 U8.1(ADJ/GND) U8.2(OUT)
NetC61_1: C61.1 U10.5(TRIM/NR)
NetC63_2: C63.2 R78.1 U9.3(IN+)
NetC64_1: C64.1 R81.2
NetC70_1: C70.1 R85.1 R86.2 U12.2(FB)
NetC70_2: C70.2 C72.2 FB3.1 R84.2 R85.2 U12.1(OUT)
NetC73_1: C73.1 R83.1
NetC74_2: C74.2 U12.6(NR/SS)
NetC117_2: C117.2 R192.1 U16.3(IN+)
NetD10_1: D10.1(A) R71.1
NetD12_1: D12.1(A) R74.1
NetD14_2: D14.2(K) R84.1
NetR72_1: R72.1 R73.1 R77.2 U9.1(OUT)
NetR72_2: R72.2 R78.2 R81.1 R189.2 R192.2 R193.2 R194.2 R195.2
NetR73_2: R73.2 R206.1 U9.4(IN-)
NetR82_1: R82.1 U11.5(~{ERR})
NetR189_1: R189.1 R190.1 R191.2 U16.1(OUT)
NetR190_2: R190.2 R207.1 U16.4(IN-)
NetR193_1: R193.1 U19.2(OUT)
NetR194_1: R194.1 TP56.1
NetR195_1: R195.1 U10.6(VOUT)

Not connected (* = marked no-connect by the designer): U10 1(DNC) 3(TEMP) 7(NC) 8(DNC); U11 2(SNS)* 3(SD)* 6(VTAP)*; U12 7(DNC)*

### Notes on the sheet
- LDO power supply section
- (near U10) +2.5V Reference

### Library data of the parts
C45 C55 C68 = C2012X5R1H475K125AB: CAP, CERM, 4.7uF, 50V, +/-10%, X5R, 0805; Manufacturer: TDK; Polarized: N; CompType: Capacitor; U/M: EA; Cap_F: 0.0000047; Tolerance_%: 10; Value1: Unknown; VDC_V: 50; TaMin_C: -55; TaMax_C: 85; Cap_Case: 0805
C46 C51 C56 C58 C69 C71 C118 C119 = C0603C104K5RACTU: CAP, CERM, 0.1uF, 50V, +/-10%, X7R, 0603; Manufacturer: Kemet; Polarized: N; CompType: Capacitor; U/M: EA; Cap_F: 0.0000001; Tolerance_%: 10; Value1: Unknown; VDC_V: 50; TaMin_C: -55; TaMax_C: 125
C49 C50 = GRM188R61H105KAALD: CAP, CERM, 1uF, 50V, +/-10%, X5R, 0603; Manufacturer: TDK; Polarized: N; CompType: Capacitor; U/M: EA; Cap_F: 0.000001; Tolerance_%: 10; Value1: Unknown; VDC_V: 50; TaMin_C: -55; TaMax_C: 85
C53 C116 = C0603C104J4RACTU: CAP, CERM, 0.1uF, 16V, +/-5%, X7R, 0603; Manufacturer: Kemet; Polarized: N; CompType: Capacitor; U/M: EA; Cap_F: 0.0000001; Tolerance_%: 5; Value1: Unknown; VDC_V: 16; TaMin_C: -55; TaMax_C: 125
C54 C70 C74 = 06031C103JAT2A: 10000pF 100V Ceramic Capacitor X7R 0603; Manufacturer: AVX; Polarized: N; Value: 0.01uF; U/M: EA; Cap_F: 0.00000001; Tolerance_%: 5; ESR_ohm: 0.098; Value1: 0.098 ohm; VDC_V: 100; TaMin_C: -55; TaMax_C: 125; AEC Category: Q200
C57 C60 C67 C72 = GMK325AB7106MM-T: CAP, CERM, 10uF, 35V, +/-20%, X7R, 1210; Manufacturer: Taiyo Yuden; Polarized: N; CompType: Capacitor; U/M: EA; Cap_F: 0.00001; Tolerance_%: 20; Value1: Unknown; VDC_V: 35; TaMin_C: -55; TaMax_C: 125
C59 = UMK107ABJ474KA-T: CAP, CERM, 0.47uF, 50V, 10%, X5R, 0603; Manufacturer: Taiyo Yuden; Polarized: N; CompType: Capacitor; Cap_F: 0.00000047; Tolerance_%: 10; VDC_V: 50
C61 C62 = C0805C105K8RACTU: CAP, CERM, 1uF, 10V, +/-10%, X7R, 0805; Manufacturer: Kemet; Polarized: N; CompType: Capacitor; U/M: EA; Cap_F: 0.000001; Tolerance_%: 10; ESR_Ohm: 0.015; Value1: 0.015 ohm; IRMS_A: 8.19; TaMin_C: -55; TaMax_C: 125; Cap_Case: 0805
C63 C117 = C0603C104K8RACTU: CAP, CERM, 0.1uF, 10V, +/-10%, X7R, 0603; Manufacturer: Kemet; Polarized: N; CompType: Capacitor; U/M: EA; Cap_F: 0.0000001; Tolerance_%: 10; Value1: Unknown; TaMin_C: -55; TaMax_C: 125
C64 = EMK107BBJ106MA-T: CAP, CERM, 10uF, 16V, +/-20%, X5R, 0603; Manufacturer: Taiyo Yuden; Polarized: N; CompType: Capacitor; U/M: EA; Cap_F: 0.00001; Tolerance_%: 20; Value1: Unknown; VDC_V: 16; TaMin_C: -55; TaMax_C: 85
C65 = GRM31CR71E106KA12L: CAP, CERM, 10uF, 25V, +/-10%, X7R, 1206; Manufacturer: Wurth; Polarized: N; CompType: Capacitor; U/M: EA; Cap_F: 0.00001; Tolerance_%: 10; Value1: Unknown; VDC_V: 25; TaMin_C: -55; TaMax_C: 125; Cap_Case: 2220
C66 = 06033C104JAT2A: as C103 on sheet TIDA-00834E2_Pg6_VOLTAGE2
C73 = C0805C225K8RACTU: CAP, CERM, 2.2uF, 10V, +/-10%, X7R, 0805; Manufacturer: Kemet; Polarized: N; CompType: Capacitor; U/M: EA; Cap_F: 0.0000022; Tolerance_%: 10; ESR_Ohm: 0.008; Value1: 0.008 ohm; IRMS_A: 15.55; TaMin_C: -55; TaMax_C: 125; Cap_Case: 0805
C122 = C1608X5R1V335K080AC: CAP, CERM, 3.3 µF, 35 V, +/- 10%, X5R, 0603; Manufacturer: TDK; Polarized: N; CompType: Capacitor; Value: 3.3uF; U/M: EA; Cap_F: 0.0000033; Tolerance_%: 10; ESR_ohm: 0.004796; Value1: 0.004796 ohm; VDC_V: 35; Value2: 35V; IRMS_A: 2.37519; TaMin_C: -55; TaMax_C: 85; SizeArea_mm2: 1.28; SizeAreaWB_mm2: 4.68; SizeX_mm: 1.6; SizeY_mm: 0.8; SizeZ_mm: 1; AEC Category: Q200
D8 = MMSZ4685-V: Diode, Zener, 3.6V, 500mW, SOD-123; Manufacturer: On semiconductor; U/M: EA; Power_W: 0.5; Vz_V: 3.6; Value1: 0.5W; RJA_CperW: 67
D10 D12 D14 = LG L29K-G2J1-24-Z: LED, Green, SMD; Manufacturer: OSRAM; Vf_V: 1.7; Value2: 1.7V; Io_A: 0.002; Tjmax_C: 110; Value1: W; U/M: EA
D11 D13 = DZ2W15000L: as D5 on sheet TIDA-00834E2_Pg7_Split Rail Converter
D23 = MMSZ5232B-7-F: Diode, Zener, 5.6 V, 500 mW, SOD-123; Manufacturer: Diodes Inc.; SymbolCreator: a0412235; U/M: EA; Power_W: 0.5; Vz_V: 5.6; Value1: 0.5W; RJA_CperW: 350; AEC Category: Q101
D24 = BAS316,115: Diode, Ultrafast, 100 V, 0.25 A, SOD-323; Manufacturer: NXP Semiconductor; U/M: EA; Vf_V: 1.4; Value: 100V; Value1: 0.25A; Value2: 1.4V; Io_A: 0.25; Vr_V: 100; TJmax_C: 150; AEC Category: Q101
FB1-FB3 = MMZ1608B102CTA00: Ferrite Bead, 1000 ohm @ 100 MHz, 0.3 A, 0603; Manufacturer: TDK; Imax_A: 0.3; DCR_ohm: 0.6; Value1: 0.6 ohm; Value2: 0.3A; ZTyp@100MHz_Ohm: 1000
J13 J47 = 5-146280-3: Header, 2.54mm, 3x1, Gold, TH; Manufacturer: TE Connectivity; SymbolCreator: a0799628; Pitch_mm: 2.54; Gender: Male; Shrouded: N; Row_Count: 1
R71 = CRCW0603300RJNEA: RES, 300 ohm, 5%, 0.1W, 0603; Manufacturer: Vishay-Dale; CompType: Resistor; Value_Code: 300R; Tolerance_%: 5; Power_W: 0.1; VDC_V: 75; TempCo: 200 ppm/C; EIA_Code: E24; U/M: EA
R72 R73 R77 R78 R81 R83 R189-R195 R206 R207 = CRCW06030000Z0EA: RES, 0 ohm, 5%, 0.1W, 0603; Manufacturer: Vishay-Dale; CompType: Resistor; Value_Code: 0000; Tolerance_%: 5; Power_W: 0.1; VDC_V: 75; TempCo: 200 ppm/C; EIA_Code: E24; U/M: EA
R74 R84 = CRCW06033K90JNEA: RES, 3.9k ohm, 5%, 0.1W, 0603; Manufacturer: Vishay-Dale; CompType: Resistor; Res_ohm: 3900; Value_Code: 3k90; Tolerance_%: 5; Power_W: 0.1; VDC_V: 75; TempCo: 200 ppm/C; EIA_Code: E24; U/M: EA
R75 R76 = CRCW12062K00FKEA: RES, 2.00 k, 1%, 0.25 W, 1206; Manufacturer: Vishay-Dale; CompType: Resistor; Value: 2.00k; Res_ohm: 2000; Value_Code: 2k00; Tolerance_%: 1; Power_W: 0.25; Value2: 0.25W; VDC_V: 200; TempCo: 100 ppm/C; SizeArea_mm2: 5.12; SizeX_mm: 3.2; SizeY_mm: 1.6; SizeZ_mm: 1.35; EIA_Code: E96; U/M: EA; AEC Category: Q200
R79 = CRCW06038K45FKEA: RES, 8.45 k, 1%, 0.1 W, 0603; Manufacturer: Vishay-Dale; CompType: Resistor; Value: 8.45k; Res_ohm: 8450; Value_Code: 8k45; Tolerance_%: 1; Power_W: 0.1; Value2: 0.1W; VDC_V: 75; TempCo: 100 ppm/C; SizeArea_mm2: 1.28; SizeX_mm: 1.6; SizeY_mm: 0.8; EIA_Code: E96; U/M: EA; AEC Category: Q200
R80 = CRCW0603100KFKEA: RES, 100 k, 1%, 0.1 W, 0603; Manufacturer: Vishay-Dale; CompType: Resistor; Value: 100k; Res_ohm: 100000; Tolerance_%: 1; Power_W: 0.1; Value2: 0.1W; VDC_V: 75; TempCo: 100 ppm/C; SizeArea_mm2: 1.28; SizeX_mm: 1.6; SizeY_mm: 0.8; EIA_Code: E96; U/M: EA; AEC Category: Q200
R82 = RNCF0603TKY10K0: as R143 on sheet TIDA-00834E2_Pg6_VOLTAGE2
R85 = CRCW06031M07FKEA: RES, 1.07 M, 1%, 0.1 W, 0603; Manufacturer: Vishay-Dale; CompType: Resistor; Value: 1.07Meg; Res_ohm: 1070000; Value_Code: 1M07; Tolerance_%: 1; Power_W: 0.1; Value2: 0.1W; VDC_V: 75; TempCo: 100 ppm/C; SizeArea_mm2: 1.28; SizeX_mm: 1.6; SizeY_mm: 0.8; EIA_Code: E96; U/M: EA; AEC Category: Q200
R86 = RC0603FR-07100KL: RES, 100 k, 1%, 0.1 W, 0603; Manufacturer: Yageo America; CompType: Resistor; Value: 100k; Res_ohm: 100000; Tolerance_%: 1; Power_W: 0.1; Value2: 0.1W; VDC_V: 150; TempCo: 200 ppm/C; EIA_Code: E96; U/M: EA; AEC Category: Q200
R87 = CRCW060331K6FKEA: RES, 31.6k ohm, 1%, 0.1W, 0603; Manufacturer: Vishay-Dale; CompType: Resistor; U/M: EA; Res_ohm: 31600; Value_Code: 31k6; Tolerance_%: 1; Power_W: 0.1; VDC_V: 75; TempCo: 100 ppm/C; EIA_Code: E96
R88 = CRCW060310K0FKEA: RES, 10.0k ohm, 1%, 0.1W, 0603; Manufacturer: Vishay-Dale; CompType: Resistor; U/M: EA; Res_ohm: 10000; Value_Code: 10k0; Tolerance_%: 1; Power_W: 0.1; VDC_V: 75; TempCo: 100 ppm/C; EIA_Code: E96
SH-J10 SH-J38 = 881545-2: as SH-J19-SH-J21 on sheet TIDA-00834E2_Pg6_VOLTAGE2
TP19 TP20 TP22 = TP-040_RND: Test Point 40mil pad 20mil drill; Manufacturer: STD; Value: STD
TP21 TP55 TP56 = 1573-2: as TP42 on sheet TIDA-00834E2_Pg6_VOLTAGE2
TP23 = 5010: Test Point, Multipurpose, Red, TH; Manufacturer: Keystone; CompType: Test Point Loop; U/M: EA
TP24 = 5126: Test Point, Multipurpose, Green, TH; Manufacturer: Keystone; SymbolCreator: a0412235; CompType: Test Point Loop; U/M: EA
U7 = TPS7A6533QKVURQ1: IC, 300-mA 40-V LOW-DROPOUT REGULATOR WITH 25-uA QUIESCENT CURRENT; Manufacturer: TI; Alternate Manufacturer: None; Area: 136210
U8 = TLV1117-XXCDCY: IC,  vvV, 800mA LDO Voltage Regulators; Manufacturer: TI; Alternate Manufacturer: None; Area: 101500; Value: TLV1117I-xxCDCY
U9 U16 = OPA322AIDBVR: 20 MHz, Low Noise, RRIO, CMOS Operational Amplifier with Shutdown, 1.8 to 5.5 V, -40 to 125 degC, 5-pin SOT23 (DBV0005A), Green (RoHS & no Sb/Br); Manufacturer: Texas Instruments; Alternate Manufacturer: None; Alternate PartNumber: Equivalent; CMRR(Min)(dB): 90; GBW(Typ)(MHz): 20; IIB(Max)(pA): 10; Iq per channel(Max)(mA): 1.9; Number of Channels: 1; Offset Drift(Typ)(uV/C): 1.8; Packing: LARGE T&R; Rating: Catalog; Sub Family: High Output Current Amplifier (>=50mA), Low Input Bias Current Amp (<=10pA), Low Noise Amp (<=10nV/rtHz), Low Supply Voltage Amplifier (<=2.7V), Precision Amplifier; Total Supply Voltage(Max)(+5V is 5, +/-5V is 10): 5.5; Vio (25C)(Max)(mV): 2
U10 = REF5025AID: Low-Noise, Very Low Drift, Precision VOLTAGE REFERENCE, 2.5V, D008A; Alternate Manufacturer: None; Manufacturer: Texas Instruments; SymbolCreator: a0411947; CompType: IC; U/M: EA
U11 = LP2951CSD: Series of Adjustable Micropower Voltage Regulators, 8-pin LLP; Manufacturer: Texas Instruments; PackageTopMarking: NS*UZXYTT*2951ACB; PowerWise: N; CompType: LDO IC
U12 = TPS7A3001DGNR: Single Output High PSRR LDO, 200 mA, Adjustable -1.18 to -33 V Output, -3 to -36 V Input, with Ultra-Low Noise, 8-pin MSOP (DGN), -40 to 125 degC, Green (RoHS & no Sb/Br); Manufacturer: Texas Instruments; Alternate PartNumber: Equivalent; Accuracy(%): 1.5; Iout(Max)(A): 0.2; Iq(Typ)(mA): 0.05; SubFamily: Single Channel LDO; Vdo(Typ)(mV): 216
U19 = REF3025AIDBZR: 2.5 V, 50 ppm / degC, 50 uA Series (Bandgap) Voltage Reference, -40 to 125 degC, 3-pin SOT-23 (DBZ), Green (RoHS & no Sb/Br); Manufacturer: Texas Instruments; Alternate PartNumber: Equivalent; Initial Accuracy @ 25/deg C(%): 0.2; Iq(Max)(uA): 50; Rating: Catalog; SubFamily: Series Voltage Reference; Temp Coeff(Typ)(ppm/ degree C): 20; VI(Max)(V): 5.5; VI(Min)(V): 2.501; VO(V): 2.5

## Sheet TIDA-00834E2_Pg9_Filters.SchDoc: FILTERS AND ADC EVM  I/P CONNECTOR
size 431 x 279 mm; Date: Not shown in title block; ApprovedBy: Not shown in title block; CheckedBy: Not shown in title block; Author: Not shown in title block; CompanyName: Not shown in title block; DrawnBy: Sreenivasa; Engineer: Not shown in title block; Organization: Not shown in title block; Address1: Not shown in title block; Address2: Not shown in title block; Address3: Not shown in title block; Address4: Not shown in title block; DocumentNumber: 1; Revision: Use project parameter SCH_Rev; SheetNumber: 9; SheetTotal: 10; PageSetup: Record=PageOptions¦CenterHorizontal=True¦CenterVertical=True¦PrintScale=1.00¦XCorrection=1.00¦YCorrection=1.00¦PrintKind=0¦BorderSize=5000000¦LeftOffset=0¦BottomOffset=0¦Orientation=2¦PaperLength=1000¦PaperWidth=1000¦Scale=100¦PaperSource=15¦PrintQuality=600¦MediaType=1¦DitherType=10¦PaperKind=Letter¦PrintScaleMode=1
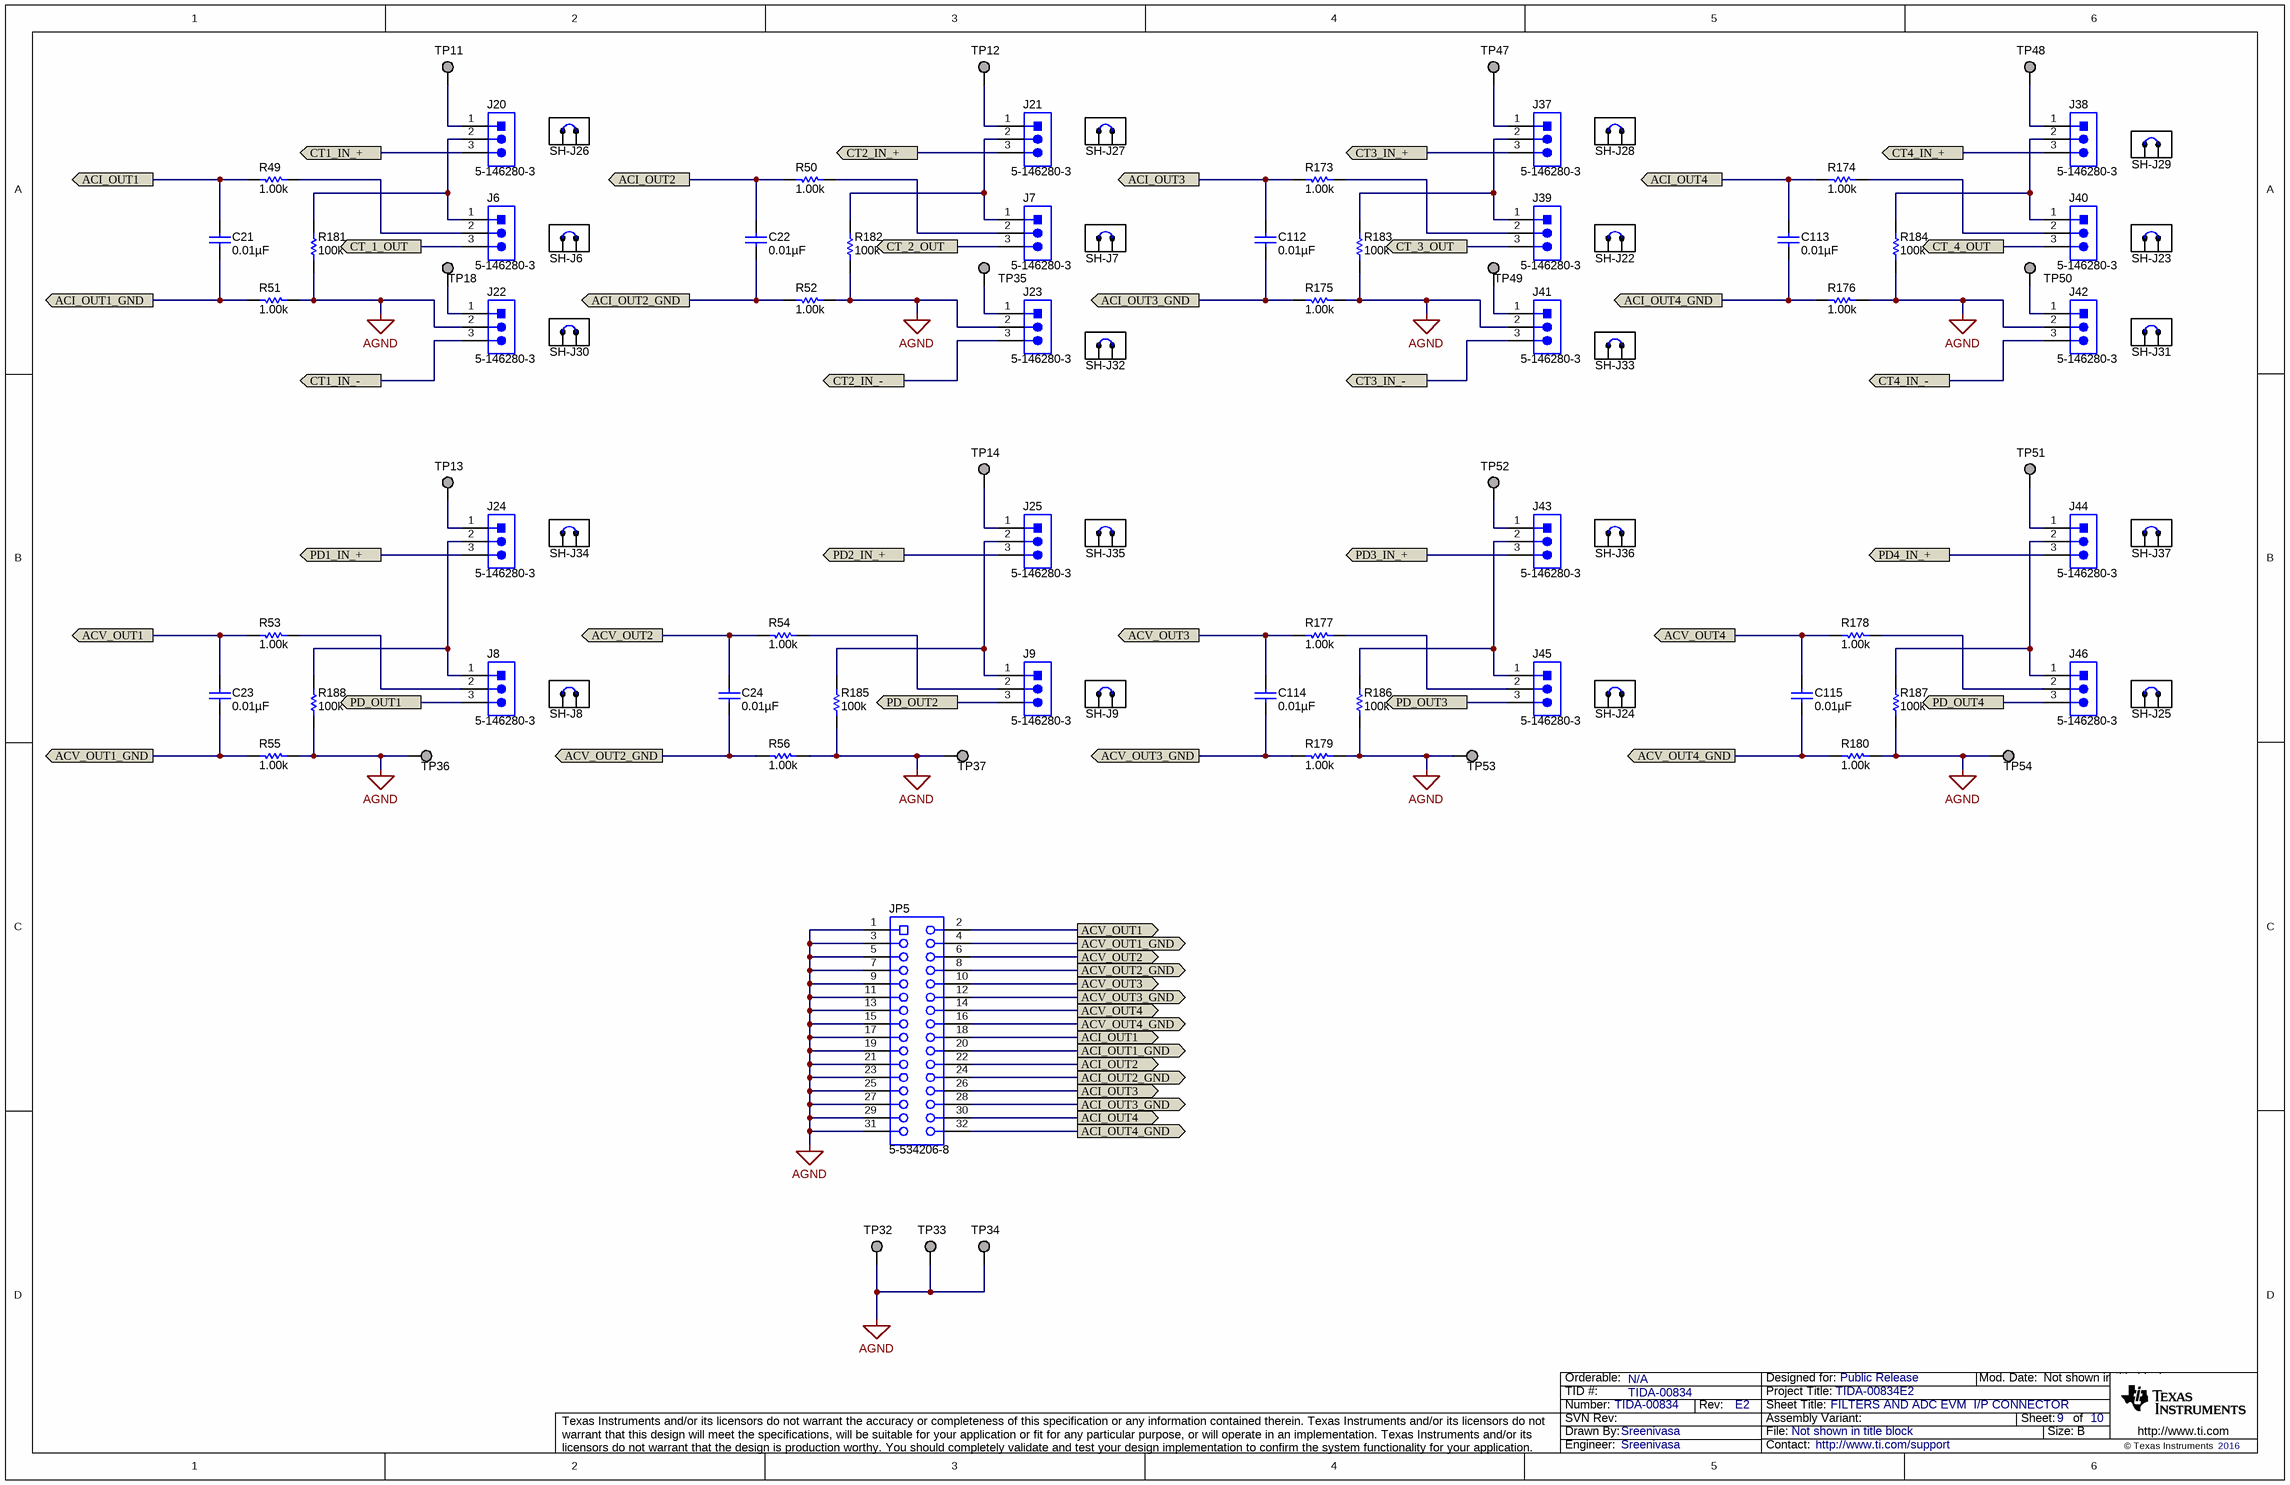
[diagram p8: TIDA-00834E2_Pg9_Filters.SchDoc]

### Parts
C21  ValueDisplayed: 0.01µF  [0805_HV]  (hidden comment: C0805C103K5RACTU)
C22  ValueDisplayed: 0.01µF  [0805_HV]  (hidden comment: C0805C103K5RACTU)
C23  ValueDisplayed: 0.01µF  [0805_HV]  (hidden comment: C0805C103K5RACTU)
C24  ValueDisplayed: 0.01µF  [0805_HV]  (hidden comment: C0805C103K5RACTU)
C112  ValueDisplayed: 0.01µF  [0805_HV]  (hidden comment: C0805C103K5RACTU)
C113  ValueDisplayed: 0.01µF  [0805_HV]  (hidden comment: C0805C103K5RACTU)
C114  ValueDisplayed: 0.01µF  [0805_HV]  (hidden comment: C0805C103K5RACTU)
C115  ValueDisplayed: 0.01µF  [0805_HV]  (hidden comment: C0805C103K5RACTU)
J6  5-146280-3  [TE_5-146280-3]
J7  5-146280-3  [TE_5-146280-3]
J8  5-146280-3  [TE_5-146280-3]
J9  5-146280-3  [TE_5-146280-3]
J20  5-146280-3  [TE_5-146280-3]
J21  5-146280-3  [TE_5-146280-3]
J22  5-146280-3  [TE_5-146280-3]
J23  5-146280-3  [TE_5-146280-3]
J24  5-146280-3  [TE_5-146280-3]
J25  5-146280-3  [TE_5-146280-3]
J37  5-146280-3  [TE_5-146280-3]
J38  5-146280-3  [TE_5-146280-3]
J39  5-146280-3  [TE_5-146280-3]
J40  5-146280-3  [TE_5-146280-3]
J41  5-146280-3  [TE_5-146280-3]
J42  5-146280-3  [TE_5-146280-3]
J43  5-146280-3  [TE_5-146280-3]
J44  5-146280-3  [TE_5-146280-3]
J45  5-146280-3  [TE_5-146280-3]
J46  5-146280-3  [TE_5-146280-3]
JP5  5-534206-8  [Samtec_SSW-116-01-x-D]
R49  ValueDisplayed: 1.00k  [0805_HV]  (hidden comment: CRCW08051K00FKEA)
R50  ValueDisplayed: 1.00k  [0805_HV]  (hidden comment: CRCW08051K00FKEA)
R51  ValueDisplayed: 1.00k  [0805_HV]  (hidden comment: CRCW08051K00FKEA)
R52  ValueDisplayed: 1.00k  [0805_HV]  (hidden comment: CRCW08051K00FKEA)
R53  ValueDisplayed: 1.00k  [0805_HV]  (hidden comment: CRCW08051K00FKEA)
R54  ValueDisplayed: 1.00k  [0805_HV]  (hidden comment: CRCW08051K00FKEA)
R55  ValueDisplayed: 1.00k  [0805_HV]  (hidden comment: CRCW08051K00FKEA)
R56  ValueDisplayed: 1.00k  [0805_HV]  (hidden comment: CRCW08051K00FKEA)
R173  ValueDisplayed: 1.00k  [0805_HV]  (hidden comment: CRCW08051K00FKEA)
R174  ValueDisplayed: 1.00k  [0805_HV]  (hidden comment: CRCW08051K00FKEA)
R175  ValueDisplayed: 1.00k  [0805_HV]  (hidden comment: CRCW08051K00FKEA)
R176  ValueDisplayed: 1.00k  [0805_HV]  (hidden comment: CRCW08051K00FKEA)
R177  ValueDisplayed: 1.00k  [0805_HV]  (hidden comment: CRCW08051K00FKEA)
R178  ValueDisplayed: 1.00k  [0805_HV]  (hidden comment: CRCW08051K00FKEA)
R179  ValueDisplayed: 1.00k  [0805_HV]  (hidden comment: CRCW08051K00FKEA)
R180  ValueDisplayed: 1.00k  [0805_HV]  (hidden comment: CRCW08051K00FKEA)
R181  ValueDisplayed: 100k  [0805_HV]  (hidden comment: CRCW0805100KFKEA)
R182  ValueDisplayed: 100k  [0805_HV]  (hidden comment: CRCW0805100KFKEA)
R183  ValueDisplayed: 100k  [0805_HV]  (hidden comment: CRCW0805100KFKEA)
R184  ValueDisplayed: 100k  [0805_HV]  (hidden comment: CRCW0805100KFKEA)
R185  ValueDisplayed: 100k  [0805_HV]  (hidden comment: CRCW0805100KFKEA)
R186  ValueDisplayed: 100k  [0805_HV]  (hidden comment: CRCW0805100KFKEA)
R187  ValueDisplayed: 100k  [0805_HV]  (hidden comment: CRCW0805100KFKEA)
R188  ValueDisplayed: 100k  [0805_HV]  (hidden comment: CRCW0805100KFKEA)
SH-J6  881545-2  [TE_881545-2]  (value not drawn)  (mechanical)
SH-J7  881545-2  [TE_881545-2]  (value not drawn)  (mechanical)
SH-J8  881545-2  [TE_881545-2]  (value not drawn)  (mechanical)
SH-J9  881545-2  [TE_881545-2]  (value not drawn)  (mechanical)
SH-J22  881545-2  [TE_881545-2]  (value not drawn)  (mechanical)
SH-J23  881545-2  [TE_881545-2]  (value not drawn)  (mechanical)
SH-J24  881545-2  [TE_881545-2]  (value not drawn)  (mechanical)
SH-J25  881545-2  [TE_881545-2]  (value not drawn)  (mechanical)
SH-J26  881545-2  [TE_881545-2]  (value not drawn)  (mechanical)
SH-J27  881545-2  [TE_881545-2]  (value not drawn)  (mechanical)
SH-J28  881545-2  [TE_881545-2]  (value not drawn)  (mechanical)
SH-J29  881545-2  [TE_881545-2]  (value not drawn)  (mechanical)
SH-J30  881545-2  [TE_881545-2]  (value not drawn)  (mechanical)
SH-J31  881545-2  [TE_881545-2]  (value not drawn)  (mechanical)
SH-J32  881545-2  [TE_881545-2]  (value not drawn)  (mechanical)
SH-J33  881545-2  [TE_881545-2]  (value not drawn)  (mechanical)
SH-J34  881545-2  [TE_881545-2]  (value not drawn)  (mechanical)
SH-J35  881545-2  [TE_881545-2]  (value not drawn)  (mechanical)
SH-J36  881545-2  [TE_881545-2]  (value not drawn)  (mechanical)
SH-J37  881545-2  [TE_881545-2]  (value not drawn)  (mechanical)
TP11  Suggest using a net name here  [Keystone1573-2]  (value not drawn)
TP12  Suggest using a net name here  [Keystone1573-2]  (value not drawn)
TP13  Suggest using a net name here  [Keystone1573-2]  (value not drawn)
TP14  Suggest using a net name here  [Keystone1573-2]  (value not drawn)
TP18  Suggest using a net name here  [Keystone1573-2]  (value not drawn)
TP32  Suggest using a net name here  [Keystone1573-2]  (value not drawn)
TP33  Suggest using a net name here  [Keystone1573-2]  (value not drawn)
TP34  Suggest using a net name here  [Keystone1573-2]  (value not drawn)
TP35  Suggest using a net name here  [Keystone1573-2]  (value not drawn)
TP36  Suggest using a net name here  [Keystone1573-2]  (value not drawn)
TP37  Suggest using a net name here  [Keystone1573-2]  (value not drawn)
TP47  Suggest using a net name here  [Keystone1573-2]  (value not drawn)
TP48  Suggest using a net name here  [Keystone1573-2]  (value not drawn)
TP49  Suggest using a net name here  [Keystone1573-2]  (value not drawn)
TP50  Suggest using a net name here  [Keystone1573-2]  (value not drawn)
TP51  Suggest using a net name here  [Keystone1573-2]  (value not drawn)
TP52  Suggest using a net name here  [Keystone1573-2]  (value not drawn)
TP53  Suggest using a net name here  [Keystone1573-2]  (value not drawn)
TP54  Suggest using a net name here  [Keystone1573-2]  (value not drawn)

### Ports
ACI_OUT1 (out), ACI_OUT1_GND (out), ACI_OUT2 (out), ACI_OUT2_GND (out), ACI_OUT3 (out), ACI_OUT3_GND (out), ACI_OUT4 (out), ACI_OUT4_GND (out), ACV_OUT1 (out), ACV_OUT1_GND (out), ACV_OUT2 (out), ACV_OUT2_GND (out), ACV_OUT3 (out), ACV_OUT3_GND (out), ACV_OUT4 (out), ACV_OUT4_GND (out), CT1_IN_+ (out), CT1_IN_- (out), CT2_IN_+ (out), CT2_IN_- (out), CT3_IN_+ (out), CT3_IN_- (out), CT4_IN_+ (out), CT4_IN_- (out), CT_1_OUT (out), CT_2_OUT (out), CT_3_OUT (out), CT_4_OUT (out), PD1_IN_+ (out), PD2_IN_+ (out), PD3_IN_+ (out), PD4_IN_+ (out), PD_OUT1 (out), PD_OUT2 (out), PD_OUT3 (out), PD_OUT4 (out)

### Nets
AGND: J22.2 J23.2 J41.2 J42.2 JP5.1 JP5.3 JP5.5 JP5.7 JP5.9 JP5.11 JP5.13 JP5.15 JP5.17 JP5.19 JP5.21 JP5.23 JP5.25 JP5.27 JP5.29 JP5.31 R51.1 R52.1 R55.1 R56.1 R175.1 R176.1 R179.1 R180.1 R181.1 R182.1 R183.1 R184.1 R185.1 R186.1 R187.1 R188.1 TP32.1 TP33.1 TP34.1 TP36.1 TP37.1 TP53.1 TP54.1
ACI_OUT1: C21.1 JP5.18 R49.2 ; port ACI_OUT1
ACI_OUT1_GND: C21.2 JP5.20 R51.2 ; port ACI_OUT1_GND
ACI_OUT2: C22.1 JP5.22 R50.2 ; port ACI_OUT2
ACI_OUT2_GND: C22.2 JP5.24 R52.2 ; port ACI_OUT2_GND
ACI_OUT3: C112.1 JP5.26 R173.2 ; port ACI_OUT3
ACI_OUT3_GND: C112.2 JP5.28 R175.2 ; port ACI_OUT3_GND
ACI_OUT4: C113.1 JP5.30 R174.2 ; port ACI_OUT4
ACI_OUT4_GND: C113.2 JP5.32 R176.2 ; port ACI_OUT4_GND
ACV_OUT1: C23.1 JP5.2 R53.2 ; port ACV_OUT1
ACV_OUT1_GND: C23.2 JP5.4 R55.2 ; port ACV_OUT1_GND
ACV_OUT2: C24.1 JP5.6 R54.2 ; port ACV_OUT2
ACV_OUT2_GND: C24.2 JP5.8 R56.2 ; port ACV_OUT2_GND
ACV_OUT3: C114.1 JP5.10 R177.2 ; port ACV_OUT3
ACV_OUT3_GND: C114.2 JP5.12 R179.2 ; port ACV_OUT3_GND
ACV_OUT4: C115.1 JP5.14 R178.2 ; port ACV_OUT4
ACV_OUT4_GND: C115.2 JP5.16 R180.2 ; port ACV_OUT4_GND
CT1_IN_+: J20.3 ; port CT1_IN_+
CT1_IN_-: J22.3 ; port CT1_IN_-
CT2_IN_+: J21.3 ; port CT2_IN_+
CT2_IN_-: J23.3 ; port CT2_IN_-
CT3_IN_+: J37.3 ; port CT3_IN_+
CT3_IN_-: J41.3 ; port CT3_IN_-
CT4_IN_+: J38.3 ; port CT4_IN_+
CT4_IN_-: J42.3 ; port CT4_IN_-
CT_1_OUT: J6.3 ; port CT_1_OUT
CT_2_OUT: J7.3 ; port CT_2_OUT
CT_3_OUT: J39.3 ; port CT_3_OUT
CT_4_OUT: J40.3 ; port CT_4_OUT
PD1_IN_+: J24.3 ; port PD1_IN_+
PD2_IN_+: J25.3 ; port PD2_IN_+
PD3_IN_+: J43.3 ; port PD3_IN_+
PD4_IN_+: J44.3 ; port PD4_IN_+
PD_OUT1: J8.3 ; port PD_OUT1
PD_OUT2: J9.3 ; port PD_OUT2
PD_OUT3: J45.3 ; port PD_OUT3
PD_OUT4: J46.3 ; port PD_OUT4
NetJ6_1: J6.1 J20.2 R181.2
NetJ6_2: J6.2 R49.1
NetJ7_1: J7.1 J21.2 R182.2
NetJ7_2: J7.2 R50.1
NetJ8_1: J8.1 J24.2 R188.2
NetJ8_2: J8.2 R53.1
NetJ9_1: J9.1 J25.2 R185.2
NetJ9_2: J9.2 R54.1
NetJ20_1: J20.1 TP11.1
NetJ21_1: J21.1 TP12.1
NetJ22_1: J22.1 TP18.1
NetJ23_1: J23.1 TP35.1
NetJ24_1: J24.1 TP13.1
NetJ25_1: J25.1 TP14.1
NetJ37_1: J37.1 TP47.1
NetJ37_2: J37.2 J39.1 R183.2
NetJ38_1: J38.1 TP48.1
NetJ38_2: J38.2 J40.1 R184.2
NetJ39_2: J39.2 R173.1
NetJ40_2: J40.2 R174.1
NetJ41_1: J41.1 TP49.1
NetJ42_1: J42.1 TP50.1
NetJ43_1: J43.1 TP52.1
NetJ43_2: J43.2 J45.1 R186.2
NetJ44_1: J44.1 TP51.1
NetJ44_2: J44.2 J46.1 R187.2
NetJ45_2: J45.2 R177.1
NetJ46_2: J46.2 R178.1

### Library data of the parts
C21-C24 C112-C115 = C0805C103K5RACTU: CAP, CERM, 0.01 µF, 50 V, +/- 10%, X7R, 0805; Manufacturer: Kemet; Polarized: N; CompType: Capacitor; Value: 0.01uF; U/M: EA; Cap_F: 0.00000001; Tolerance_%: 10; ESR_ohm: 1.739; Value1: 1.739 ohm; VDC_V: 50; Value2: 50V; IRMS_A: 0.411; TaMin_C: -55; TaMax_C: 125; Cap_Case: 0805; SizeArea_mm2: 2.5; SizeAreaWB_mm2: 6.75; SizeX_mm: 2; SizeY_mm: 1.25; SizeZ_mm: 1.45; AEC Category: Q200
J6-J9 J20-J25 J37-J46 = 5-146280-3: as J13 on sheet TIDA-00834E2_Pg8_LDO
JP5 = SSW-116-01-G-D: Receptacle, 2.54mm, 16x2, Gold, TH; Manufacturer: Samtec; SymbolCreator: a0411947; Pitch_mm: 2.54; Gender: Female; Row_Count: 2; Current_A: 6.3; Voltage_V: 550; Cert_CSA: Y
R49-R56 R173-R180 = CRCW08051K00FKEA: RES, 1.00 k, 1%, 0.125 W, 0805; Manufacturer: Vishay-Dale; CompType: Resistor; Value: 1.00k; Res_ohm: 1000; Value_Code: 1k00; Tolerance_%: 1; Power_W: 0.125; Value2: 0.125W; VDC_V: 150; TempCo: 100 ppm/C; SizeArea_mm2: 2.5; SizeX_mm: 2; SizeY_mm: 1.25; SizeZ_mm: 1.45; EIA_Code: E96; U/M: EA; AEC Category: Q200
R181-R188 = CRCW0805100KFKEA: RES, 100 k, 1%, 0.125 W, 0805; Manufacturer: Vishay-Dale; CompType: Resistor; Value: 100k; Res_ohm: 100000; Tolerance_%: 1; Power_W: 0.125; Value2: 0.125W; VDC_V: 150; TempCo: 100 ppm/C; SizeArea_mm2: 2.5; SizeX_mm: 2; SizeY_mm: 1.25; SizeZ_mm: 1.45; EIA_Code: E96; U/M: EA; AEC Category: Q200
SH-J6-SH-J9 SH-J22-SH-J37 = 881545-2: as SH-J19-SH-J21 on sheet TIDA-00834E2_Pg6_VOLTAGE2
TP11-TP14 TP18 TP32-TP37 TP47-TP54 = 1573-2: as TP42 on sheet TIDA-00834E2_Pg6_VOLTAGE2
